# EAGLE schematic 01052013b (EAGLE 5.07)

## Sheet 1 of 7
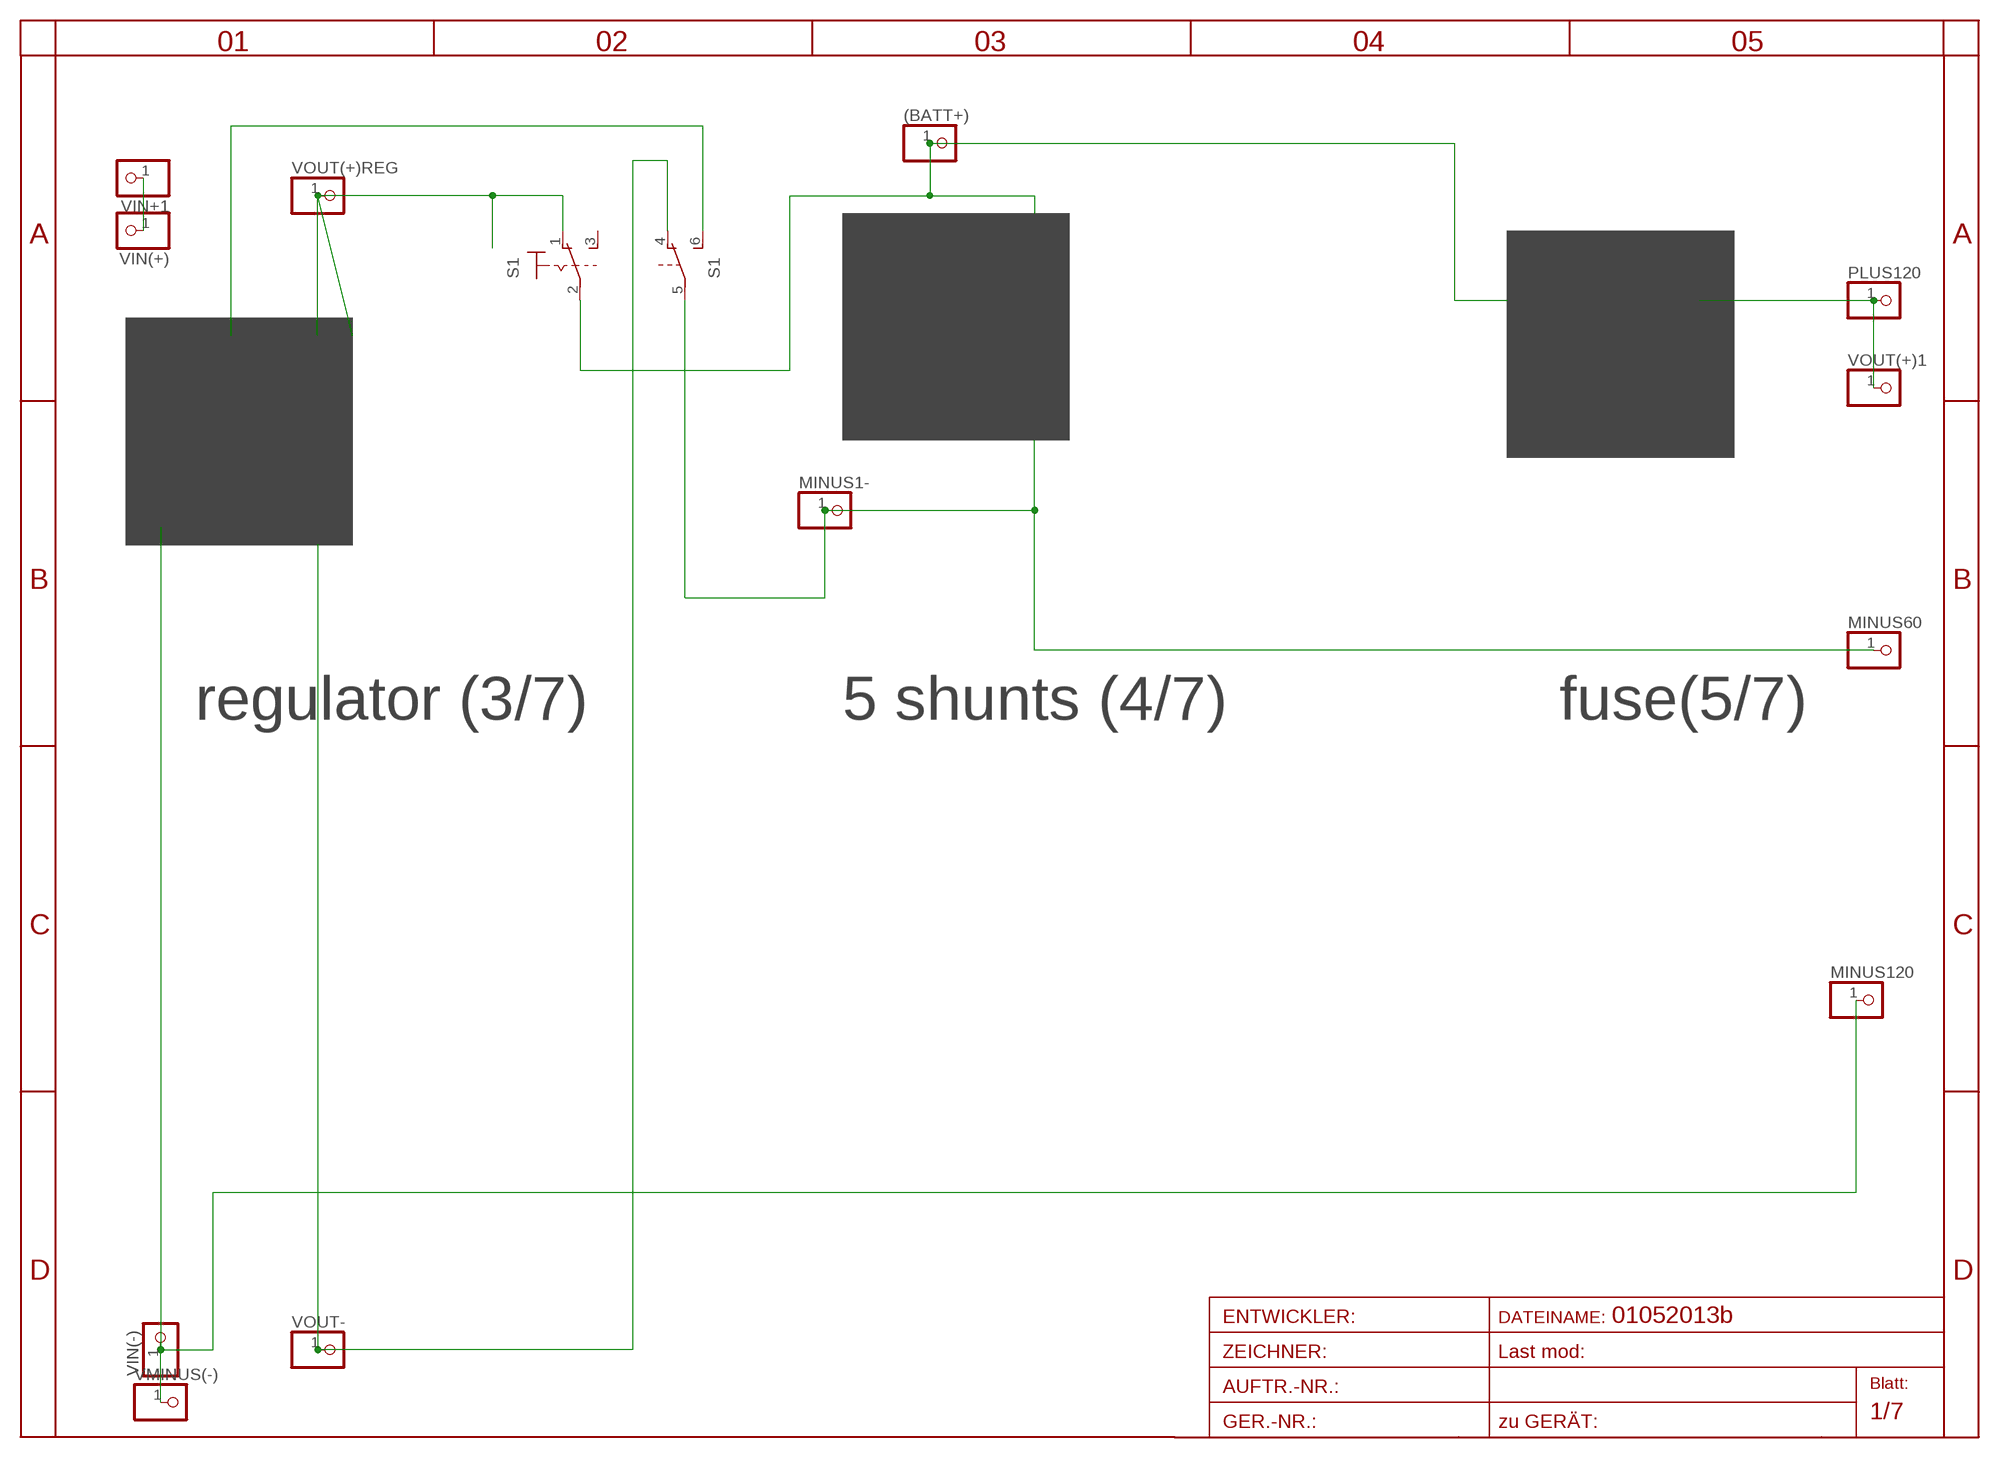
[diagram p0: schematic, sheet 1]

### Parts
(BATT+)  PINHD-1X14.5MM  [1X4MM5]
MINUS1-  PINHD-1X14.5MM  [1X4MM5]
MINUS60  PINHD-1X14.5MM  [1X4MM5]
MINUS120  PINHD-1X14.5MM  [1X4MM5]
PLUS120  PINHD-1X14.5MM  [1X4MM5]
S1  320-938320NEW  [320NEW]
VIN(+)  PINHD-1X11MM6  [1X1MM8]
VIN(-)  PINHD-1X1  [1X01]
VIN+1  PINHD-1X1  [1X01]
VMINUS(-)  PINHD-1X11MM6  [1X1MM8]
VOUT(+)1  PINHD-1X11X0.4  [1X01]
VOUT(+)REG  PINHD-1X11X0.4  [1X01]
VOUT-  PINHD-1X11X0.4  [1X01]

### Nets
BATT-: MINUS1-.1 MINUS60.1 S1.5(B:P) ; also sheet 4,5,6,7
IN-: MINUS120.1 VIN(-).1 VMINUS(-).1 ; also sheet 3
PLUS11: (BATT+).1 S1.2(1:P) ; also sheet 4,5,6,7
V+OUT: PLUS120.1 VOUT(+)1.1 ; also sheet 5
V-: S1.4(B:O) VOUT-.1 ; also sheet 3
VIN+: S1.6(B:S) ; also sheet 3
VINX: VIN(+).1 VIN+1.1 ; also sheet 3
VOUT+REG: S1.1(1:O) VOUT(+)REG.1 ; also sheet 3
Unconnected: S1.3(1:S)

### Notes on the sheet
- regulator (3/7) | 5 shunts (4/7) | fuse(5/7)

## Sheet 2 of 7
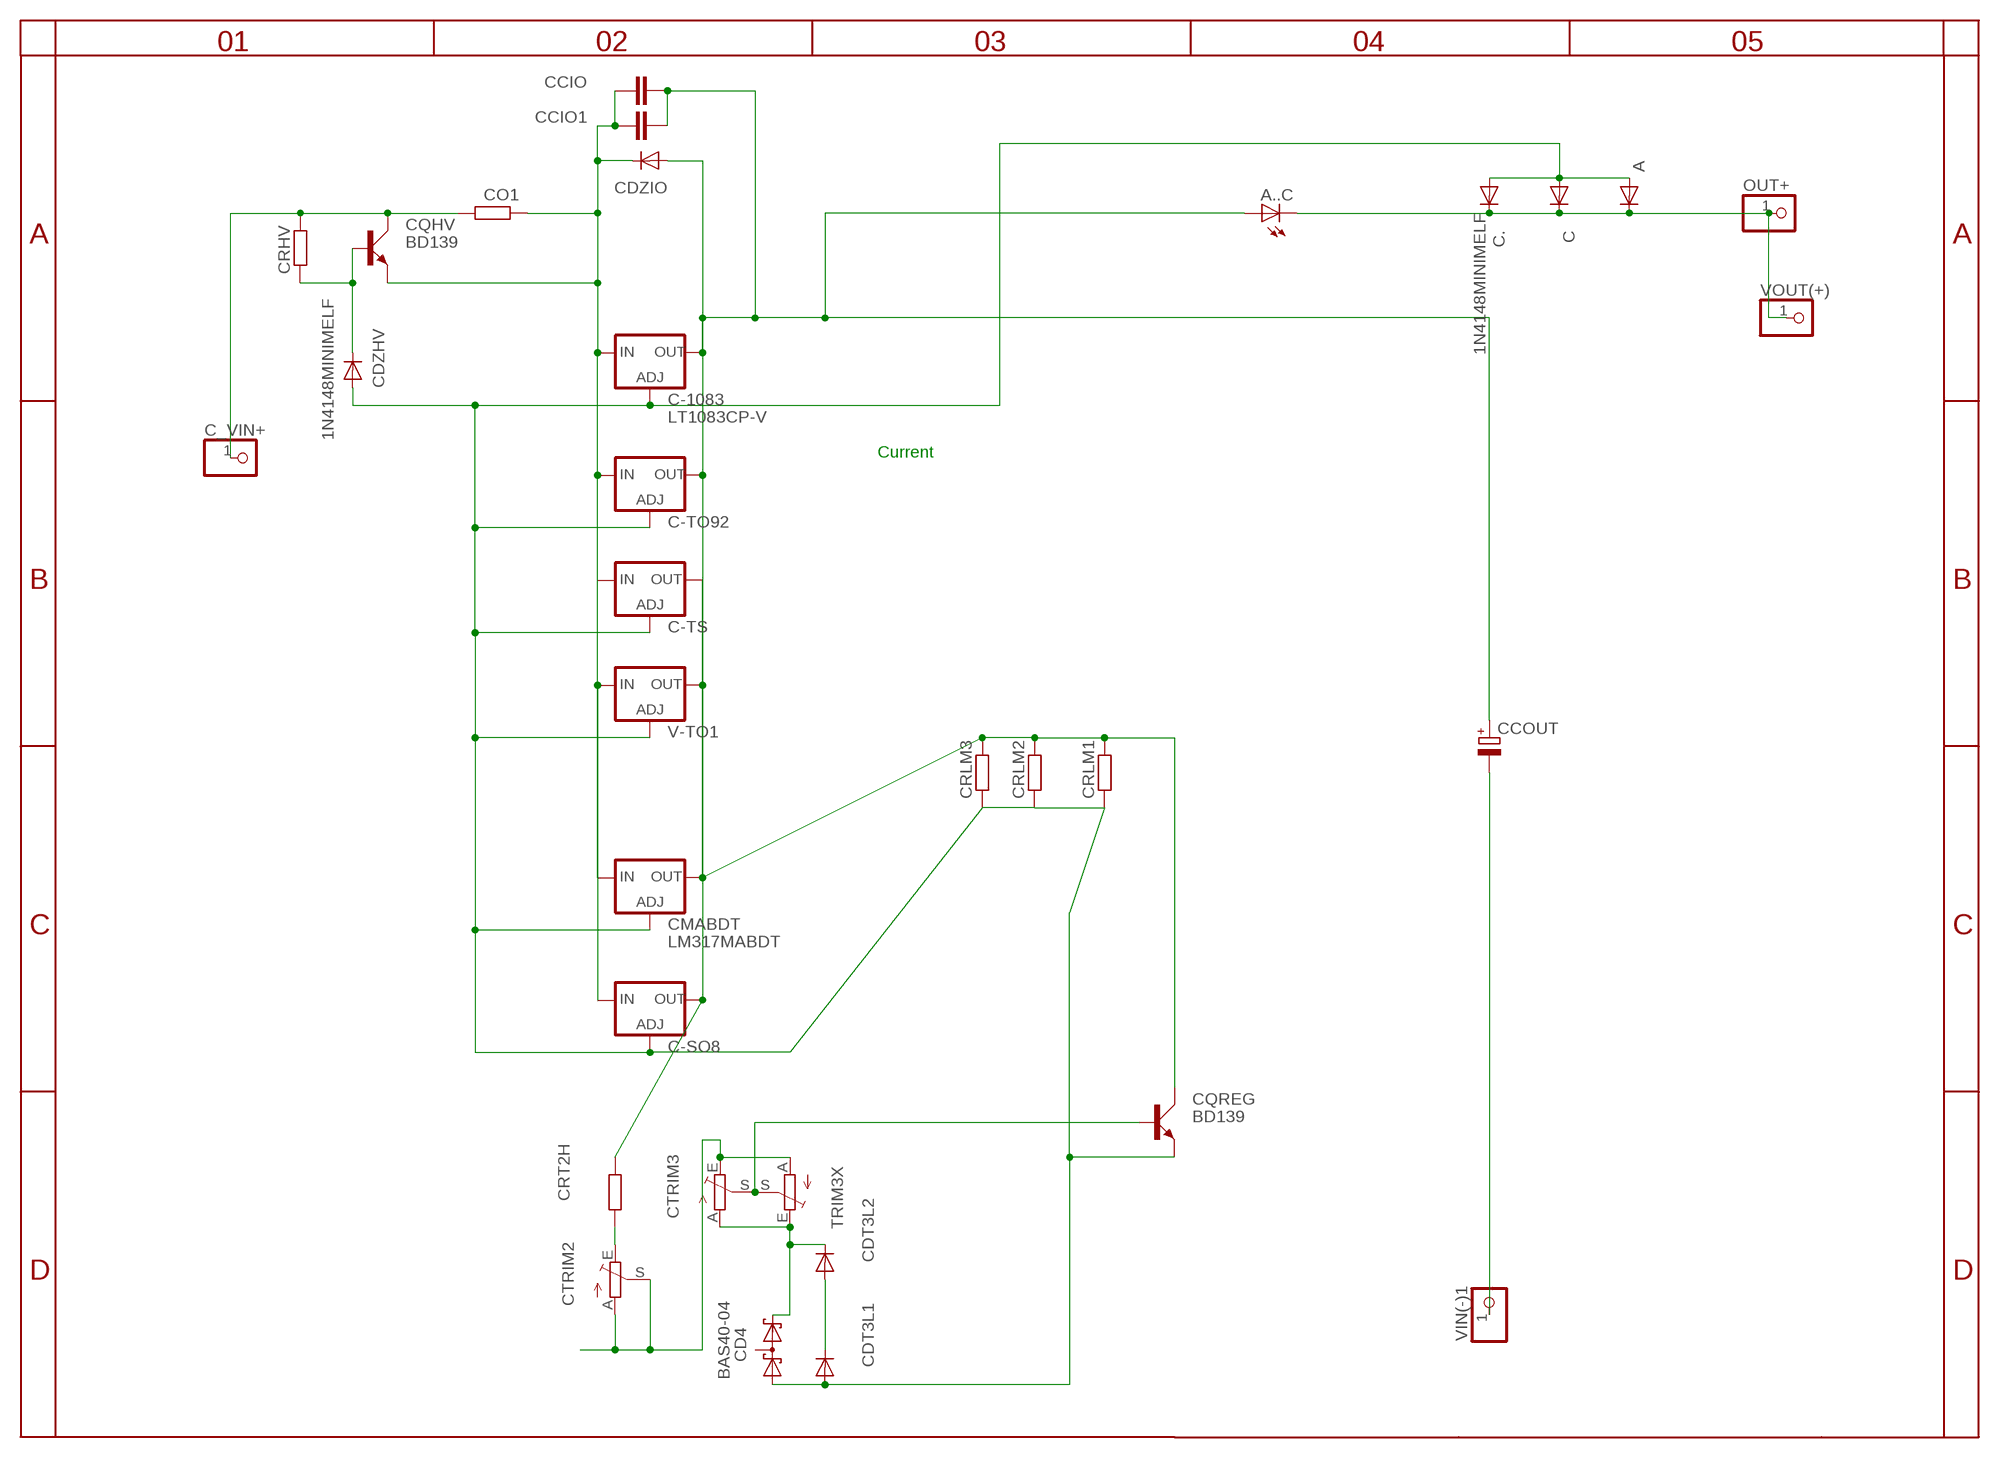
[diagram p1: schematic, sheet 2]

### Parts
A  DIODE-TO220V  [TO220ACS]
A..C  LED3MM  [LED3MM]
C  DIODE-SMB  [SMB]
C-1083  LT1083CP-V  [TO247S]
C-SO8  LM317LM-OUTPIN7  [SO08]
C-TO92  LM317LZS  [TO92S]
C-TS  LM317TS  [317TS]
C.  1N4148MINIMELF  [MINIMELF]
C_VIN+  PINHD-1X11MM6  [1X1MM8]
CCIO  C-EUC1206  [C1206]
CCIO1  C-EU050-025X075  [C050-025X075]
CCOUT  CPOL-EUE5-6  [E5-6]
CD4  BAS40-04  [SOT23]
CDT3L1  DIODE-MINIMELF  [MINIMELF]
CDT3L2  DIODE-MINIMELF  [MINIMELF]
CDZHV  1N4148MINIMELF  [MINIMELF]
CDZIO  DIODE-MINIMELF  [MINIMELF]
CMABDT  LM317MABDT  [DPACK]
CO1  R-EU_R0805  [R0805]
CQHV  BD139  [TO126AV]
CQREG  BD139  [TO126AV]
CRHV  R-EU_R1206  [R1206]
CRLM1  R-EU_R5025  [R5025]
CRLM2  R-EU_R1210  [R1210]
CRLM3  R-EU_R1206  [R1206]
CRT2H  R-EU_R1206  [R1206]
CTRIM2  TRIM_EU-EVND_H  [EVND8AA]
CTRIM3  TRIM_EU-EVND_H  [EVND8AA]
OUT+  PINHD-1X1  [1X01]
TRIM3X  TRIM_EU-RAND160  [RANDL]
V-TO1  LM317-TO3  [TO3-K02]
VIN(-)1  PINHD-1X1  [1X01]
VOUT(+)  PINHD-1X11X0.4  [1X01]

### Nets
ADJUST: A.A C-1083.1(ADJ) C-SO8.4(ADJ) C-TO92.1(ADJ) C-TS.1(ADJ) C..A C.A CD4.1(A1) CDT3L1.A CDZHV.A CMABDT.1(ADJ) CQREG.E CRLM1.1 CRLM2.1 CRLM3.1 V-TO1.2(ADJ)
B1: CQREG.B CTRIM3.S TRIM3X.S
CVIN: C_VIN+.1 CO1.2 CQHV.C CRHV.2
INPUT+: C-1083.3(IN) C-SO8.1(IN) C-TO92.3(IN) C-TS.3(IN) CCIO1.1 CCIO.1 CDZIO.C CMABDT.3(IN) CO1.1 CQHV.E V-TO1.1(IN)
MINUS: CD4.2(C2) CDT3L2.C CTRIM3.A TRIM3X.E
N$5: CTRIM2.A CTRIM2.S CTRIM3.E TRIM3X.A
N$6: CRT2H.1 CTRIM2.E
N$9: CCOUT.- VIN(-)1.1
N$54: CDT3L1.C CDT3L2.A
N$84: CDZHV.C CQHV.B CRHV.1
OUT1: A..C.A C-1083.2(OUT) C-SO8.7(OUT) C-TO92.2(OUT) C-TS.2(OUT) CCIO1.2 CCIO.2 CCOUT.+ CDZIO.A CMABDT.4(OUT) CQREG.C CRLM1.2 CRLM2.2 CRLM3.2 CRT2H.2 V-TO1.3(OUT)
OUT+: A..C.K(C) A.C C..C C.C OUT+.1 VOUT(+).1
Unconnected: CD4.3(C1A2)

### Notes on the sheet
- Current

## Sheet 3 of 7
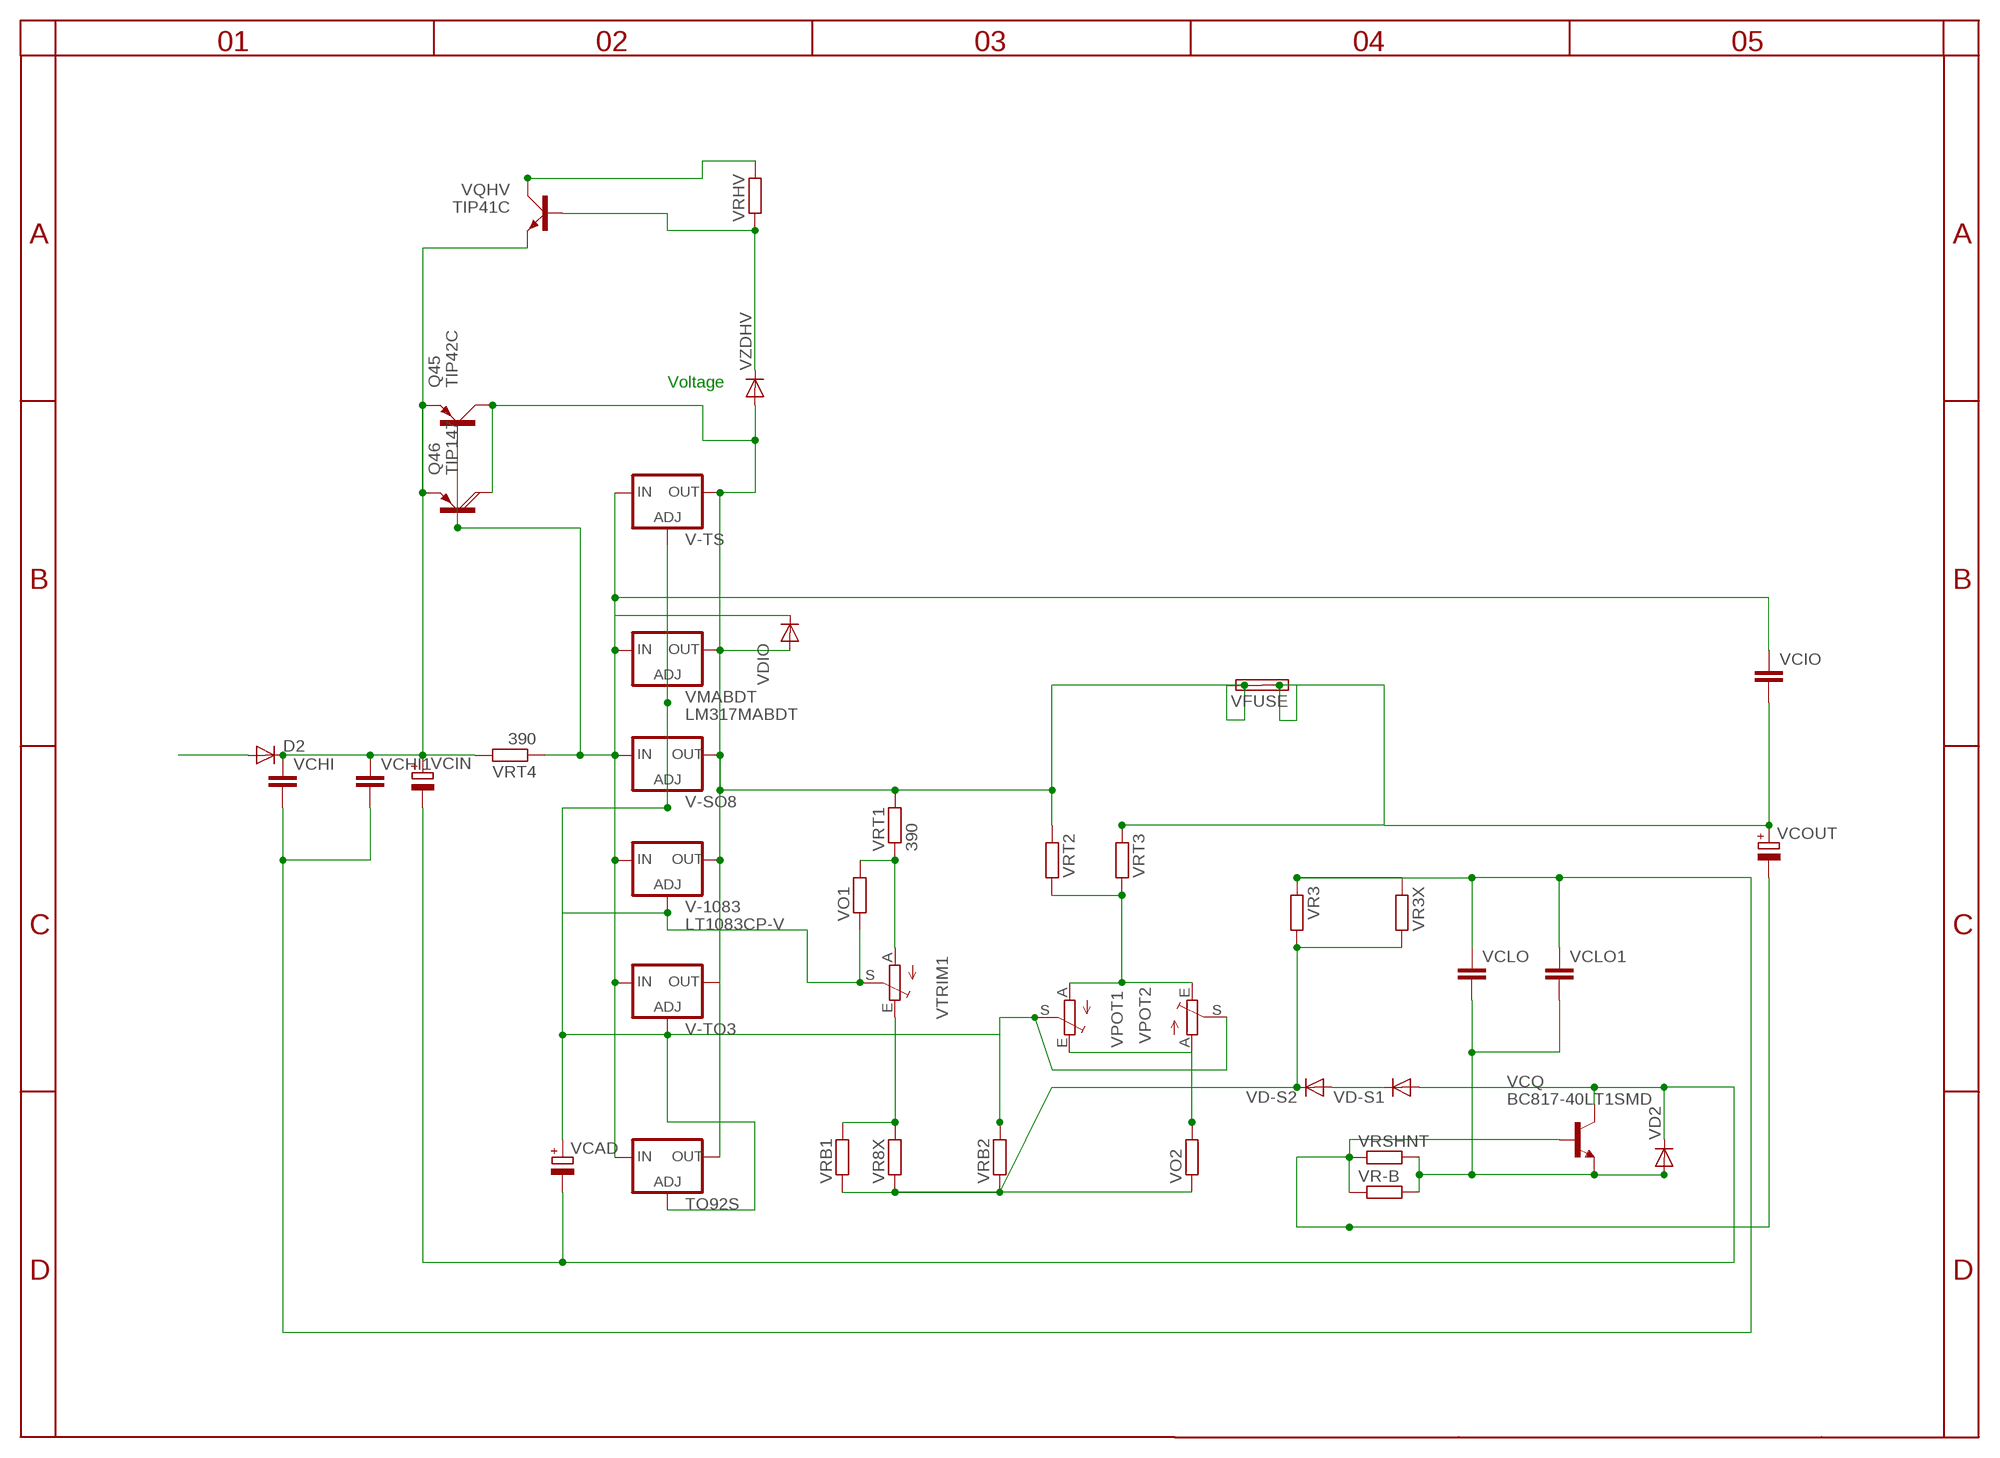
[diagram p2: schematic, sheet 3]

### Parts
D2  DIODE-SMC  [SMC]
Q45  TIP42C  [TO220AV]
Q46  TIP147  TIP147V  [SOT93V]
TO92S  LM317LZS  [TO92S]
V-1083  LT1083CP-V  [TO247S]
V-SO8  LM317LM-OUTPIN7  [SO08]
V-TO3  LM317-TO3  [TO3-K02]
V-TS  LM317TS  [317TS]
VCAD  CPOL-EUE2.5-6  [E2,5-6]
VCHI  C-EU050-025X075  [C050-025X075]
VCHI1  C-EUC1206  [C1206]
VCIN  CPOL-EUE2.5-6  [E2,5-6]
VCIO  C-EUC1206  [C1206]
VCLO  C-EU050-025X075  [C050-025X075]
VCLO1  C-EUC1206  [C1206]
VCOUT  CPOL-EUE5-8.5  [E5-8,5]
VCQ  BC817-40LT1SMD  [SOT23-BEC]
VD2  DIODE-MINIMELF  [MINIMELF]
VD-S1  DIODE-MINIMELF  [MINIMELF]
VD-S2  DIODE-MINIMELF  [MINIMELF]
VDIO  DIODE-MINIMELF  [MINIMELF]
VFUSE  SHK20Q  [SHK20Q]
VMABDT  LM317MABDT  [DPACK]
VO1  R-EU_0204/2V  [0204V]
VO2  R-EU_0204/2V  [0204V]
VPOT1  TRIM_EU-RAND160  [RANDL]
VPOT2  TRIM_EU-S64W  [S64W]
VQHV  TIP41C  [TO220AV]
VR3  R-EU_0204/5  [0204/5]
VR3X  R-EU_R1206  [R1206]
VR8X  R-EU_0204/2V  [0204V]
VR-B  R-EU_R2010  [R2010]
VRB1  R-EU_R1206  [R1206]
VRB2  R-EU_R1206  [R1206]
VRHV  R-EU_R1206  [R1206]
VRSHNT  R-EU_0617/17  [0617/17]
VRT1  390  R-EU_0207/15  [0207/15]
VRT2  R-EU_R1206  [R1206]
VRT3  R-EU_R1206  [R1206]
VRT4  390  R-EU_0207/10  [0207/10]
VTRIM1  TRIM_EU-EVND_H  [EVND8AA]
VZDHV  DIODE-MINIMELF  [MINIMELF]

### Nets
ADJ2: TO92S.1(ADJ) V-1083.1(ADJ) V-SO8.4(ADJ) V-TO3.2(ADJ) V-TS.1(ADJ) VCAD.+ VMABDT.1(ADJ) VO1.1 VPOT1.S VPOT2.S VRB2.2 VTRIM1.S
IN+1: Q45.B Q46.B TO92S.3(IN) V-1083.3(IN) V-SO8.1(IN) V-TO3.1(IN) V-TS.3(IN) VCIO.1 VDIO.C VMABDT.3(IN) VRT4.1
IN-: VCLO1.2 VCLO.2 VCQ.E VD2.A VR-B.2 VRSHNT.2 ; also sheet 1
N$1: VO2.2 VPOT1.E VPOT2.A
N$2: VPOT1.A VPOT2.E VRT2.2 VRT3.2
N$3: VR8X.2 VRB1.2 VTRIM1.E
N$4: VO1.2 VRT1.1 VTRIM1.A
N$7: VCHI1.2 VCHI.2 VCLO1.1 VCLO.1 VR3.1 VR3X.1
N$10: VQHV.B VRHV.1 VZDHV.C
N$12: VD-S2.C VO2.1 VR3.2 VR3X.2 VR8X.1 VRB1.1 VRB2.1
N$13: VD-S1.C VD-S2.A
N$166: D2.C Q45.E Q46.E VCHI1.1 VCHI.1 VCIN.+ VQHV.E VRT4.2
OUT2: Q45.C Q46.C TO92S.2(OUT) V-1083.2(OUT) V-SO8.7(OUT) V-TO3.3(OUT) V-TS.2(OUT) VDIO.A VFUSE.2A VFUSE.2B VMABDT.4(OUT) VRT1.2 VRT2.1 VZDHV.A
V-: VCOUT.- VCQ.B VR-B.1 VRSHNT.1 ; also sheet 1
VIN+: VQHV.C VRHV.2 ; also sheet 1
VINX: D2.A ; also sheet 1
VIRT-: VCAD.- VCIN.- VCQ.C VD2.C VD-S1.A
VOUT+REG: VCIO.2 VCOUT.+ VFUSE.1A VFUSE.1B VRT3.1 ; also sheet 1

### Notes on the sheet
- Voltage

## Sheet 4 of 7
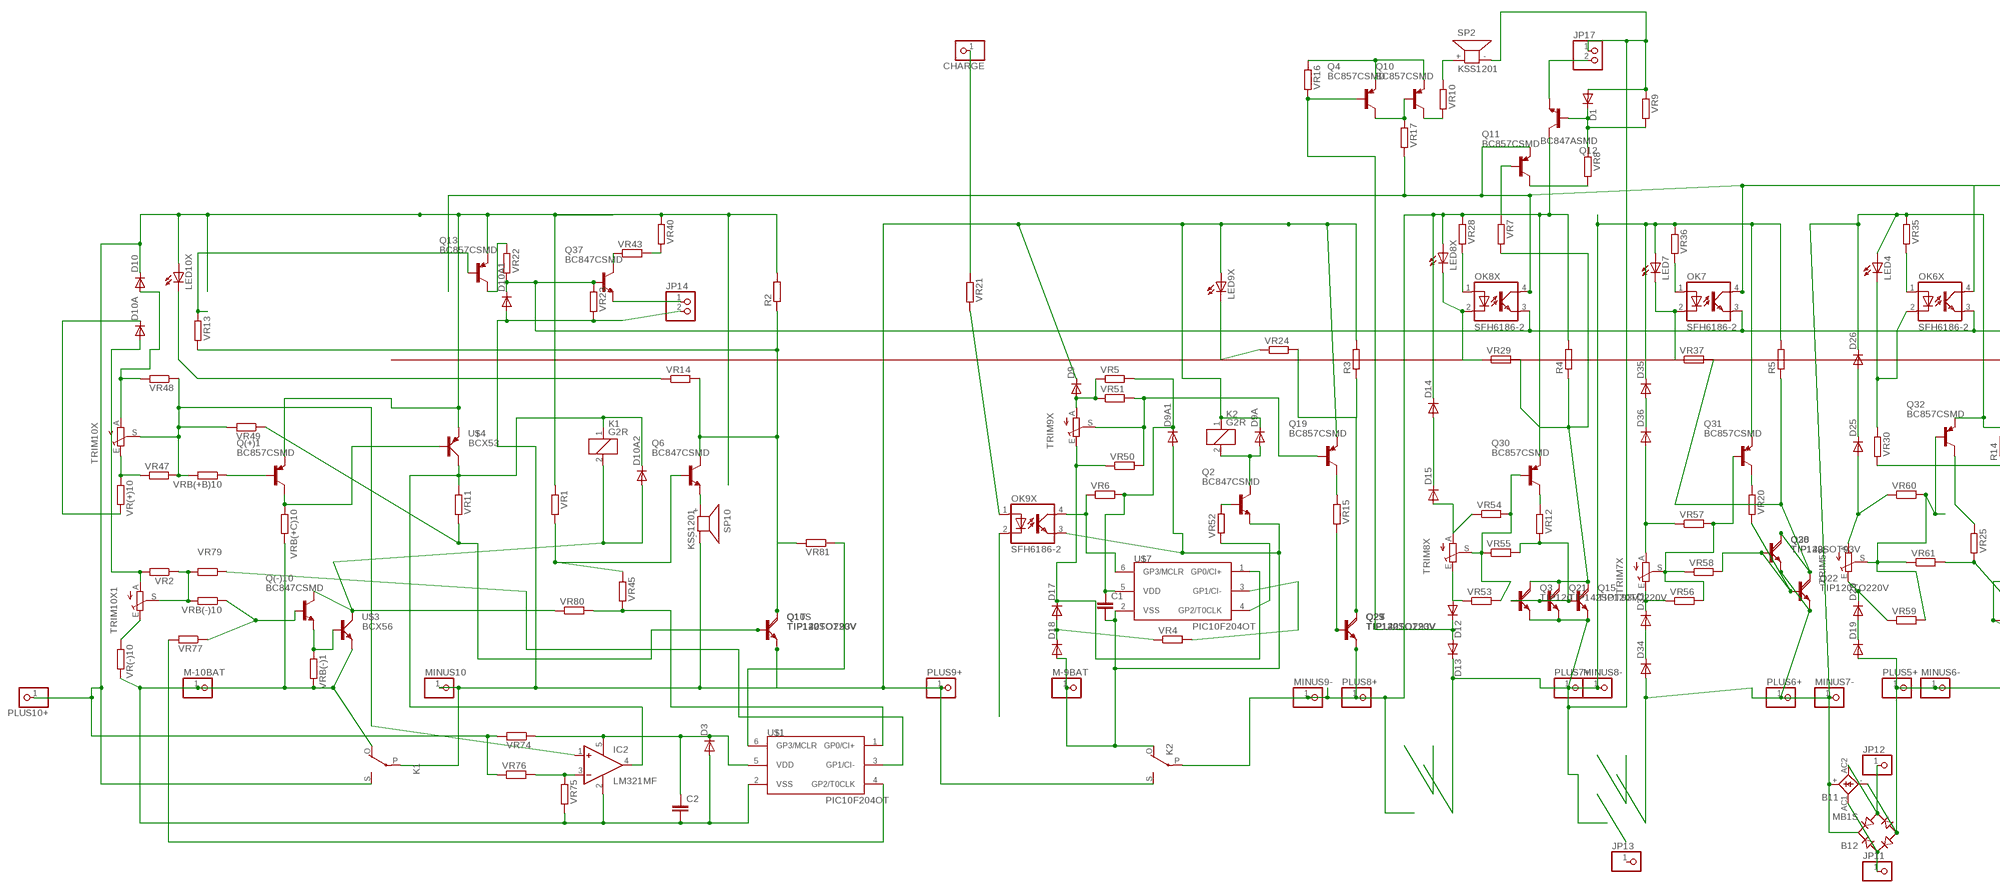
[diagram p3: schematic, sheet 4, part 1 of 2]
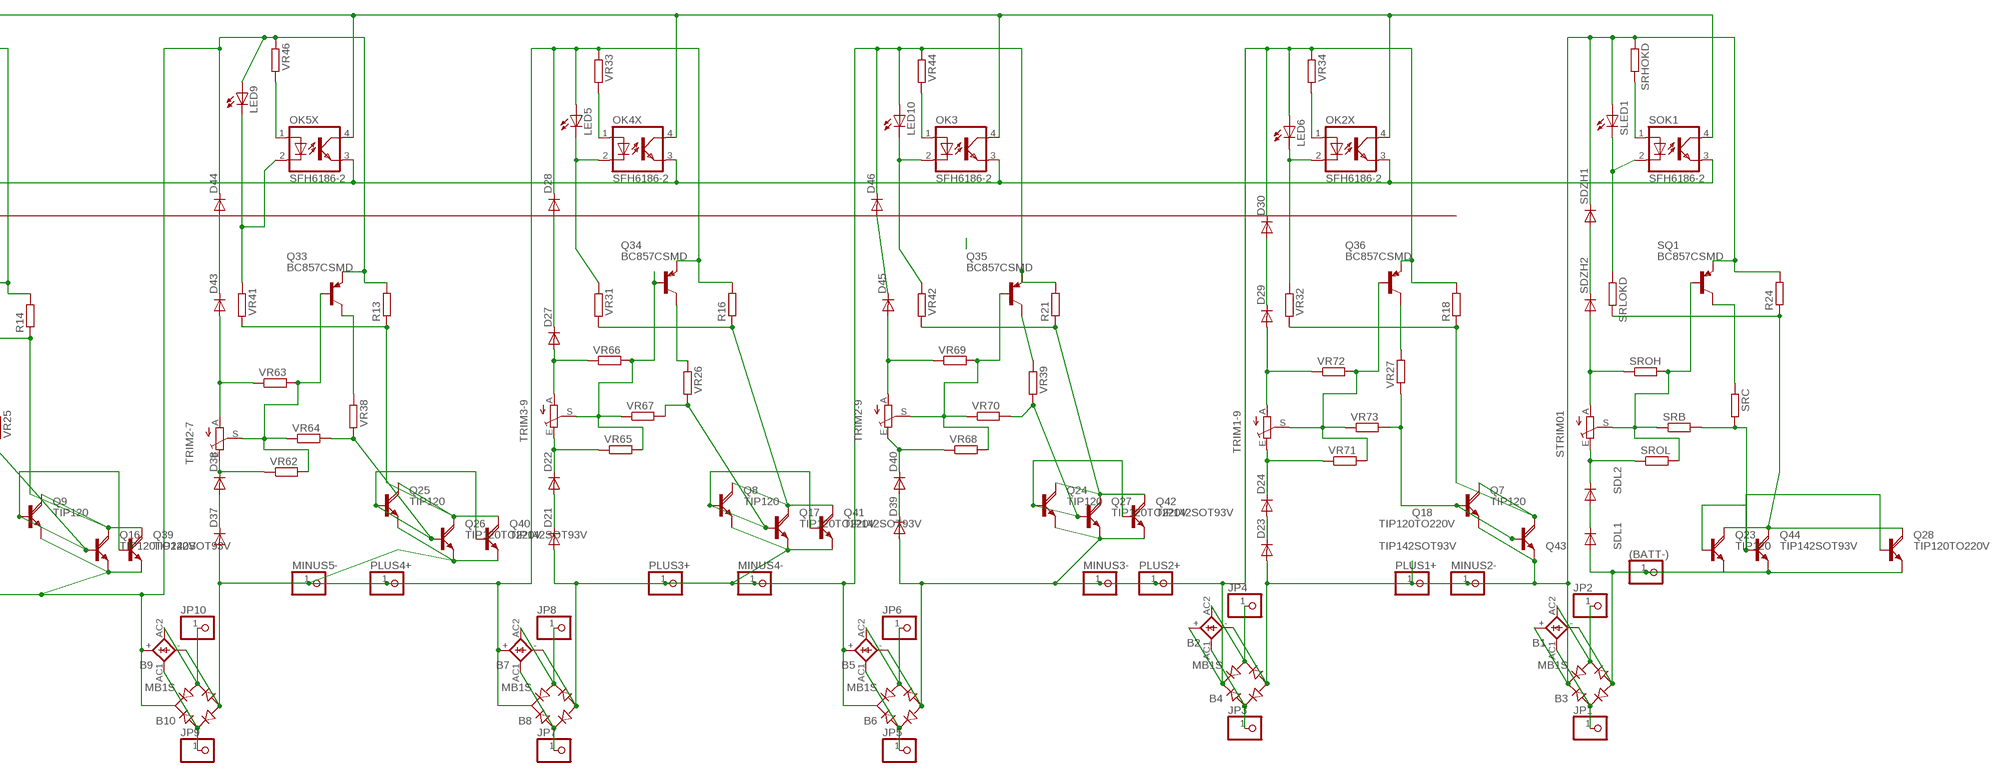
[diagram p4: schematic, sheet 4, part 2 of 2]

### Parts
(BATT-)  PINHD-1X11X0.4  [1X01]
B1  2KBP  [2KBP]
B2  2KBP  [2KBP]
B3  MB1S  [SOIC-4]
B4  MB1S  [SOIC-4]
B5  2KBP  [2KBP]
B6  MB1S  [SOIC-4]
B7  2KBP  [2KBP]
B8  MB1S  [SOIC-4]
B9  2KBP  [2KBP]
B10  MB1S  [SOIC-4]
B11  2KBP  [2KBP]
B12  MB1S  [SOIC-4]
C1  C-EUC0805  [C0805]
C2  C-EUC0805  [C0805]
CHARGE  PINHD-1X11X0.4  [1X01]
D1  DIODE-MINIMELF  [MINIMELF]
D3  DIODE-MINIMELF  [MINIMELF]
D9  DIODE-MINIMELF  [MINIMELF]
D9A  DIODE-MINIMELF  [MINIMELF]
D9A1  DIODE-MINIMELF  [MINIMELF]
D10  DIODE-MINIMELF  [MINIMELF]
D10A  DIODE-MINIMELF  [MINIMELF]
D10A1  DIODE-MINIMELF  [MINIMELF]
D10A2  DIODE-MINIMELF  [MINIMELF]
D12  DIODE-MINIMELF  [MINIMELF]
D13  DIODE-MINIMELF  [MINIMELF]
D14  DIODE-MINIMELF  [MINIMELF]
D15  DIODE-MINIMELF  [MINIMELF]
D17  DIODE-MINIMELF  [MINIMELF]
D18  DIODE-MINIMELF  [MINIMELF]
D19  DIODE-MINIMELF  [MINIMELF]
D20  DIODE-MINIMELF  [MINIMELF]
D21  DIODE-MINIMELF  [MINIMELF]
D22  DIODE-MINIMELF  [MINIMELF]
D23  DIODE-MINIMELF  [MINIMELF]
D24  DIODE-MINIMELF  [MINIMELF]
D25  DIODE-MINIMELF  [MINIMELF]
D26  DIODE-MINIMELF  [MINIMELF]
D27  DIODE-MINIMELF  [MINIMELF]
D28  DIODE-MINIMELF  [MINIMELF]
D29  DIODE-MINIMELF  [MINIMELF]
D30  DIODE-MINIMELF  [MINIMELF]
D33  DIODE-MINIMELF  [MINIMELF]
D34  DIODE-MINIMELF  [MINIMELF]
D35  DIODE-MINIMELF  [MINIMELF]
D36  DIODE-MINIMELF  [MINIMELF]
D37  DIODE-MINIMELF  [MINIMELF]
D38  DIODE-MINIMELF  [MINIMELF]
D39  DIODE-MINIMELF  [MINIMELF]
D40  DIODE-MINIMELF  [MINIMELF]
D43  DIODE-MINIMELF  [MINIMELF]
D44  DIODE-MINIMELF  [MINIMELF]
D45  DIODE-MINIMELF  [MINIMELF]
D46  DIODE-MINIMELF  [MINIMELF]
IC2  LM321MF  [SOT23-5]
JP1  PINHD-1X11X0.4  [1X01]
JP2  PINHD-1X11X0.4  [1X01]
JP3  PINHD-1X11X0.4  [1X01]
JP4  PINHD-1X11X0.4  [1X01]
JP5  PINHD-1X11X0.4  [1X01]
JP6  PINHD-1X11X0.4  [1X01]
JP7  PINHD-1X11X0.4  [1X01]
JP8  PINHD-1X11X0.4  [1X01]
JP9  PINHD-1X11X0.4  [1X01]
JP10  PINHD-1X11X0.4  [1X01]
JP11  PINHD-1X11X0.4  [1X01]
JP12  PINHD-1X11X0.4  [1X01]
JP13  PINHD-1X11X0.4  [1X01]
JP14  PINHD-1X2STR  [1X02]
JP17  PINHD-1X2STR  [1X02]
K1  G2R  [G2R]
K2  G2R  [G2R]
LED4  LEDCHIPLED_1206  [CHIPLED_1206]
LED5  LEDCHIPLED_1206  [CHIPLED_1206]
LED6  LEDCHIPLED_1206  [CHIPLED_1206]
LED7  LEDCHIPLED_1206  [CHIPLED_1206]
LED8X  LEDCHIPLED_1206  [CHIPLED_1206]
LED9  LEDCHIPLED_1206  [CHIPLED_1206]
LED9X  LEDCHIPLED_1206  [CHIPLED_1206]
LED10  LEDCHIPLED_1206  [CHIPLED_1206]
LED10X  LEDCHIPLED_1206  [CHIPLED_1206]
M-9BAT  PINHD-1X11X0.4  [1X01]
M-10BAT  PINHD-1X11X0.4  [1X01]
MINUS2-  PINHD-1X14.5MM  [1X4MM5]
MINUS3-  PINHD-1X14.5MM  [1X4MM5]
MINUS4-  PINHD-1X14.5MM  [1X4MM5]
MINUS5-  PINHD-1X14.5MM  [1X4MM5]
MINUS6-  PINHD-1X14.5MM  [1X4MM5]
MINUS7-  PINHD-1X14.5MM  [1X4MM5]
MINUS8-  PINHD-1X14.5MM  [1X4MM5]
MINUS9-  PINHD-1X14.5MM  [1X4MM5]
MINUS10  PINHD-1X14.5MM  [1X4MM5]
OK2X  SFH6186-2  [SMD4]
OK3  SFH6186-2  [SMD4]
OK4X  SFH6186-2  [SMD4]
OK5X  SFH6186-2  [SMD4]
OK6X  SFH6186-2  [SMD4]
OK7  SFH6186-2  [SMD4]
OK8X  SFH6186-2  [SMD4]
OK9X  SFH6186-2  [SMD4]
PLUS1+  PINHD-1X11X0.4  [1X01]
PLUS2+  PINHD-1X11X0.4  [1X01]
PLUS3+  PINHD-1X11X0.4  [1X01]
PLUS4+  PINHD-1X11X0.4  [1X01]
PLUS5+  PINHD-1X11X0.4  [1X01]
PLUS6+  PINHD-1X11X0.4  [1X01]
PLUS7+  PINHD-1X11X0.4  [1X01]
PLUS8+  PINHD-1X11X0.4  [1X01]
PLUS9+  PINHD-1X11X0.4  [1X01]
PLUS10+  PINHD-1X11X0.4  [1X01]
Q1  TIP142SOT93V  [SOT93V]
Q1T  TIP120TO220V  [TO220AV]
Q2  BC847CSMD  [SOT23]
Q2S  TIP120  TIP120DPAK  [D-PAK_TO252AA]
Q2T  TIP120TO220V  [TO220AV]
Q3  TIP120  TIP120DPAK  [D-PAK_TO252AA]
Q4  BC857CSMD  [SOT23-BEC]
Q6  BC847CSMD  [SOT23]
Q7  TIP120  TIP120DPAK  [D-PAK_TO252AA]
Q8  TIP120  TIP120DPAK  [D-PAK_TO252AA]
Q9  TIP120  TIP120DPAK  [D-PAK_TO252AA]
Q10  BC857CSMD  [SOT23-BEC]
Q10S  TIP120  TIP120DPAK  [D-PAK_TO252AA]
Q11  BC857CSMD  [SOT23-BEC]
Q12  BC847ASMD  [SOT23]
Q13  BC857CSMD  [SOT23-BEC]
Q15  TIP120TO220V  [TO220AV]
Q16  TIP120TO220V  [TO220AV]
Q17  TIP120TO220V  [TO220AV]
Q18  TIP120TO220V  [TO220AV]
Q19  BC857CSMD  [SOT23-BEC]
Q20  TIP120  TIP120DPAK  [D-PAK_TO252AA]
Q21  TIP142SOT93V  [SOT93V]
Q22  TIP120TO220V  [TO220AV]
Q23  TIP120  TIP120DPAK  [D-PAK_TO252AA]
Q24  TIP120  TIP120DPAK  [D-PAK_TO252AA]
Q25  TIP120  TIP120DPAK  [D-PAK_TO252AA]
Q26  TIP120TO220V  [TO220AV]
Q27  TIP120TO220V  [TO220AV]
Q28  TIP120TO220V  [TO220AV]
Q29  TIP142SOT93V  [SOT93V]
Q30  BC857CSMD  [SOT23-BEC]
Q31  BC857CSMD  [SOT23-BEC]
Q32  BC857CSMD  [SOT23-BEC]
Q33  BC857CSMD  [SOT23-BEC]
Q34  BC857CSMD  [SOT23-BEC]
Q35  BC857CSMD  [SOT23-BEC]
Q36  BC857CSMD  [SOT23-BEC]
Q37  BC847CSMD  [SOT23]
Q38  TIP142SOT93V  [SOT93V]
Q39  TIP142SOT93V  [SOT93V]
Q40  TIP142SOT93V  [SOT93V]
Q41  TIP142SOT93V  [SOT93V]
Q42  TIP142SOT93V  [SOT93V]
Q43  TIP142SOT93V  [SOT93V]
Q44  TIP142SOT93V  [SOT93V]
Q(+)1  BC857CSMD  [SOT23-BEC]
Q(-)10  BC847CSMD  [SOT23]
R2  R-EU_CERAM85  [CERAM85]
R3  R-EU_CERAM67  [CERAM67]
R4  R-EU_CERAM67  [CERAM67]
R5  R-EU_CERAM67  [CERAM67]
R13  R-EU_CERAM67  [CERAM67]
R14  R-EU_CERAM67  [CERAM67]
R16  R-EU_CERAM67  [CERAM67]
R18  R-EU_CERAM67  [CERAM67]
R21  R-EU_CERAM67  [CERAM67]
R24  R-EU_CERAM67  [CERAM67]
SDL1  DIODE-MINIMELF  [MINIMELF]
SDL2  DIODE-MINIMELF  [MINIMELF]
SDZH1  DIODE-MINIMELF  [MINIMELF]
SDZH2  DIODE-MINIMELF  [MINIMELF]
SLED1  LEDCHIPLED_1206  [CHIPLED_1206]
SOK1  SFH6186-2  [SMD4]
SP2  KSS1201  [KSS1201]
SP10  KSS1201  [KSS1201]
SQ1  BC857CSMD  [SOT23-BEC]
SRB  R-EU_R0805  [R0805]
SRC  R-EU_R1206  [R1206]
SRHOKD  R-EU_R1206  [R1206]
SRLOKD  R-EU_R1206  [R1206]
SROH  R-EU_R0805  [R0805]
SROL  R-EU_R0805  [R0805]
STRIM01  TRIM_EU-S64W  [S64W]
TRIM1-9  TRIM_EU-S64W  [S64W]
TRIM2-7  TRIM_EU-S64W  [S64W]
TRIM2-9  TRIM_EU-S64W  [S64W]
TRIM3-9  TRIM_EU-S64W  [S64W]
TRIM5X  TRIM_EU-S64W  [S64W]
TRIM7X  TRIM_EU-S64W  [S64W]
TRIM8X  TRIM_EU-S64W  [S64W]
TRIM9X  TRIM_EU-S64W  [S64W]
TRIM10X  TRIM_EU-S64W  [S64W]
TRIM10X1  TRIM_EU-S64W  [S64W]
U$1  PIC10F204OT  [SOT23-6]
U$3  BCX56  [SOT223]
U$4  BCX53  [SOT223]
U$7  PIC10F204OT  [SOT23-6]
VR1  R-EU_R0603  [R0603]
VR2  R-EU_R0603  [R0603]
VR4  R-EU_R0805  [R0805]
VR5  R-EU_R1206  [R1206]
VR6  R-EU_R0805  [R0805]
VR7  R-EU_R1206  [R1206]
VR8  R-EU_R1206  [R1206]
VR9  R-EU_R1206  [R1206]
VR10  R-EU_R1206  [R1206]
VR11  R-EU_R0603  [R0603]
VR12  R-EU_R1206  [R1206]
VR13  R-EU_R0603  [R0603]
VR14  R-EU_R0805  [R0805]
VR15  R-EU_R0805  [R0805]
VR16  R-EU_R1206  [R1206]
VR17  R-EU_R1206  [R1206]
VR20  R-EU_R1206  [R1206]
VR21  R-EU_R1206  [R1206]
VR22  R-EU_R0603  [R0603]
VR23  R-EU_R0603  [R0603]
VR24  R-EU_R0805  [R0805]
VR25  R-EU_R1206  [R1206]
VR26  R-EU_R1206  [R1206]
VR27  R-EU_R1206  [R1206]
VR28  R-EU_R1206  [R1206]
VR29  R-EU_R1206  [R1206]
VR30  R-EU_R1206  [R1206]
VR31  R-EU_R1206  [R1206]
VR32  R-EU_R1206  [R1206]
VR33  R-EU_R1206  [R1206]
VR34  R-EU_R1206  [R1206]
VR35  R-EU_R1206  [R1206]
VR36  R-EU_R1206  [R1206]
VR37  R-EU_R1206  [R1206]
VR38  R-EU_R1206  [R1206]
VR39  R-EU_R1206  [R1206]
VR40  R-EU_R1206  [R1206]
VR41  R-EU_R1206  [R1206]
VR42  R-EU_R1206  [R1206]
VR43  R-EU_R1206  [R1206]
VR44  R-EU_R1206  [R1206]
VR45  R-EU_R0603  [R0603]
VR46  R-EU_R1206  [R1206]
VR47  R-EU_R0603  [R0603]
VR48  R-EU_R0603  [R0603]
VR49  R-EU_R0603  [R0603]
VR50  R-EU_R0805  [R0805]
VR51  R-EU_R0805  [R0805]
VR52  R-EU_R1206  [R1206]
VR53  R-EU_R0805  [R0805]
VR54  R-EU_R0805  [R0805]
VR55  R-EU_R0805  [R0805]
VR56  R-EU_R0805  [R0805]
VR57  R-EU_R0805  [R0805]
VR58  R-EU_R0805  [R0805]
VR59  R-EU_R0805  [R0805]
VR60  R-EU_R0805  [R0805]
VR61  R-EU_R0805  [R0805]
VR62  R-EU_R0805  [R0805]
VR63  R-EU_R0805  [R0805]
VR64  R-EU_R0805  [R0805]
VR65  R-EU_R0805  [R0805]
VR66  R-EU_R0805  [R0805]
VR67  R-EU_R0805  [R0805]
VR68  R-EU_R0805  [R0805]
VR69  R-EU_R0805  [R0805]
VR70  R-EU_R0805  [R0805]
VR71  R-EU_R0805  [R0805]
VR72  R-EU_R0805  [R0805]
VR73  R-EU_R0805  [R0805]
VR74  R-EU_R0603  [R0603]
VR75  R-EU_R0603  [R0603]
VR76  R-EU_R0603  [R0603]
VR77  R-EU_R0603  [R0603]
VR79  R-EU_R0603  [R0603]
VR80  R-EU_R0603  [R0603]
VR81  R-EU_R0603  [R0603]
VR(+)10  R-EU_R1206  [R1206]
VR(-)10  R-EU_R1206  [R1206]
VRB(+B)10  R-EU_R0603  [R0603]
VRB(+C)10  R-EU_R0603  [R0603]
VRB(-)1  R-EU_R0603  [R0603]
VRB(-)10  R-EU_R0603  [R0603]

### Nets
B2: U$1.4(GP2/T0CLK) VR77.2
B10: IC2.1(+IN) TRIM10X.S VR47.2 VR48.1 VR49.2 VRB(+B)10.2
BATT-: (BATT-).1 B1.- B3.- OK9X.2(C) Q23.3(E) Q28.E Q44.E SDL1.A ; also sheet 1,5,6,7
E2: B1.+ B2.- B3.+ B4.- D23.A MINUS2-.1 PLUS1+.1 Q7.3(E) Q18.E Q43.E R24.2 SDZH1.C SLED1.A SQ1.E SRHOKD.1
E3: B2.+ B4.+ B5.- B6.- D30.C D39.A LED6.A MINUS3-.1 PLUS2+.1 Q24.3(E) Q27.E Q36.E Q42.E R18.2 VR34.1
E4: B5.+ B6.+ B7.- B8.- D21.A D46.C LED10.A MINUS4-.1 PLUS3+.1 Q8.3(E) Q17.E Q35.E Q41.E R21.2 VR44.1
E5: B7.+ B8.+ B9.- B10.- D28.C D37.A LED5.A MINUS5-.1 PLUS4+.1 Q25.3(E) Q26.E Q34.E Q40.E R16.2 VR33.1
E6: B9.+ B10.+ B11.- B12.- D19.A D44.C LED9.A MINUS6-.1 PLUS5+.1 Q9.3(E) Q16.E Q33.E Q39.E R13.2 VR46.1
E7: B11.+ B12.+ D26.C D34.A LED4.A MINUS7-.1 PLUS6+.1 Q20.3(E) Q22.E Q32.E Q38.E R14.2 VR35.1
E8: D1.A D13.C D35.C JP17.1 LED7.A MINUS8-.1 PLUS7+.1 Q3.3(E) Q15.E Q21.E Q31.E R5.2 SP2.- VR9.1 VR36.1
E9: D14.C K2.P(2:P) LED8X.A MINUS9-.1 PLUS8+.1 Q2S.3(E) Q2T.E Q12.3(C) Q29.E Q30.E R4.2 VR28.1
E10: D9.C D9A.C D10A1.A JP14.2 K1.P(2:P) K2.1 K2.S(2:S) LED9X.A MINUS10.1 PLUS9+.1 Q1.E Q1T.E Q10S.3(E) Q19.E R3.2 SP10.- VR23.2
GP3: Q6.2(E) SP10.+ ; also sheet 7
N$8: B1.AC1 B3.~1(AC1) JP1.1
N$11: LED10X.C VR14.1
N$14: D10.A TRIM10X.A VR48.2
N$15: D10A2.C IC2.4(OUT) K1.1 U$4.2(C) VR11.1
N$16: OK8X.1(A) VR28.2
N$17: D10A.A TRIM10X1.A VR2.2
N$20: D9.A TRIM9X.A VR5.1 VR51.1
N$22: TRIM10X1.S VR2.1 VR79.2 VRB(-)10.2
N$23: Q13.B VR13.1
N$24: TRIM10X1.E VR(-)10.1
N$25: Q1.B Q1T.B Q10S.1(B) VR11.2 VR49.1
N$26: D15.A TRIM8X.A VR54.1
N$27: D12.A TRIM8X.E VR53.1
N$29: D14.A D15.C
N$31: LED8X.C OK8X.2(C) VR29.1
N$32: D12.C D13.A Q4.B VR16.2
N$33: Q3.1(B) Q15.B Q21.B VR12.2 VR55.2
N$40: B1.AC2 B3.~2(AC2) JP2.1
N$45: Q35.C VR39.1
N$50: Q9.1(B) Q16.B Q39.B VR25.2 VR61.2
N$51: Q8.1(B) Q17.B Q41.B VR26.2 VR67.2
N$52: Q7.1(B) Q18.B Q43.B VR27.1 VR73.2
N$55: D33.A D34.C
N$56: C1.2 D9A1.A D18.A K2.O(2:O) M-9BAT.1 OK9X.3(EMIT) Q2.2(E) U$7.2(VSS)
N$57: D33.C TRIM7X.E VR56.1
N$58: B2.AC1 B4.~1(AC1) JP3.1
N$59: B2.AC2 B4.~2(AC2) JP4.1
N$60: B5.AC1 B6.~1(AC1) JP5.1
N$61: B5.AC2 B6.~2(AC2) JP6.1
N$62: D27.A TRIM3-9.A VR66.1
N$63: D22.C TRIM3-9.E VR65.1
N$64: Q34.B TRIM3-9.S VR65.2 VR66.2 VR67.1
N$65: Q31.B TRIM7X.S VR56.2 VR57.2 VR58.1
N$66: D25.A TRIM5X.A VR60.1
N$67: Q31.C VR20.1
N$68: D19.C D20.A
N$70: D21.C D22.A
N$71: D25.C D26.A
N$72: D20.C TRIM5X.E VR59.1
N$73: D27.C D28.A
N$74: D29.C D30.A
N$76: CHARGE.1 VR21.1
N$77: LED4.C OK6X.2(C) VR30.1
N$78: LED5.C OK4X.2(C) VR31.1
N$79: LED6.C OK2X.2(C) VR32.1
N$80: OK6X.1(A) VR35.2
N$81: OK4X.1(A) VR33.2
N$82: OK2X.1(A) VR34.2
N$85: B7.AC1 B8.~1(AC1) JP7.1
N$86: Q19.B TRIM9X.S VR50.2 VR51.2
N$87: Q2S.1(B) Q2T.B Q29.B VR15.2
N$88: D36.A TRIM7X.A VR57.1
N$89: D37.C D38.A
N$90: B7.AC2 B8.~2(AC2) JP8.1
N$91: D35.A D36.C
N$92: Q34.C VR26.1
N$93: Q20.1(B) Q22.B Q38.B VR20.2 VR58.2
N$94: LED9X.C VR24.1
N$95: OK9X.1(A) VR21.2
N$97: B9.AC1 B10.~1(AC1) JP9.1
N$98: B9.AC2 B10.~2(AC2) JP10.1
N$99: OK7.1(A) VR36.2
N$100: LED7.C OK7.2(C) VR37.1
N$102: Q25.1(B) Q26.B Q40.B VR38.2 VR64.2
N$103: Q24.1(B) Q27.B Q42.B VR39.2 VR70.2
N$104: Q23.1(B) Q28.B Q44.B SRB.2 SRC.2
N$105: Q32.B TRIM5X.S VR59.2 VR60.2 VR61.1
N$106: D43.A TRIM2-7.A VR63.1
N$107: Q33.C VR38.1
N$108: D29.A TRIM1-9.A VR72.1
N$109: D40.C TRIM2-9.E VR68.1
N$110: D38.C TRIM2-7.E VR62.1
N$111: Q33.B TRIM2-7.S VR62.2 VR63.2 VR64.1
N$112: Q32.C VR25.1
N$113: Q35.B TRIM2-9.S VR68.2 VR69.2 VR70.1
N$114: B11.AC1 B12.~1(AC1) JP11.1
N$115: D45.A TRIM2-9.A VR69.1
N$116: D24.C TRIM1-9.E VR71.1
N$117: B11.AC2 B12.~2(AC2) JP12.1
N$118: D43.C D44.A
N$119: D45.C D46.A
N$120: SDZH1.A SDZH2.C
N$121: LED9.C OK5X.2(C) VR41.1
N$122: LED10.C OK3.2(C) VR42.1
N$123: SLED1.C SOK1.2(C) SRLOKD.1
N$124: OK5X.1(A) VR46.2
N$125: OK3.1(A) VR44.2
N$126: SOK1.1(A) SRHOKD.2
N$127: D17.C TRIM9X.E U$7.1(GP0/CI+) VR50.1
N$128: TRIM10X.E VR47.1 VR(+)10.1
N$129: D17.A D18.C VR4.1
N$130: Q30.C VR12.1
N$131: Q19.C VR15.1
N$132: Q30.B TRIM8X.S VR53.2 VR54.2 VR55.1
N$133: D39.C D40.A
N$134: Q36.B TRIM1-9.S VR71.2 VR72.2 VR73.1
N$136: JP14.1 Q37.2(E)
N$137: D23.C D24.A
N$138: U$1.1(GP0/CI+) VR45.2 VR80.2
N$140: Q36.C VR27.2
N$141: SDZH2.A SROH.1 STRIM01.A
N$142: SDL2.C SROL.1 STRIM01.E
N$143: SQ1.B SRB.1 SROH.2 SROL.2 STRIM01.S
N$144: SDL1.C SDL2.A
N$145: SQ1.C SRC.1
N$146: Q6.1(B) VR1.2 VR45.1
N$147: Q2.1(B) VR52.2
N$148: D9A.A K2.2 Q2.3(C)
N$149: IC2.3(-IN) VR75.1 VR76.2
N$150: SP2.+ VR10.1
N$151: U$7.4(GP2/T0CLK) VR52.1
N$152: D1.C Q12.1(B) VR8.1 VR9.2
N$153: OK9X.4(COL) U$7.6(GP3/MCLR) VR6.1
N$154: U$7.3(GP1/CI-) VR4.2
N$155: Q11.C VR8.2
N$156: C1.1 D9A1.C U$7.5(VDD) VR5.2 VR6.2
N$157: JP17.2 Q12.2(E)
N$158: Q11.B VR7.1
N$159: Q13.C VR22.1
N$160: Q4.E Q10.E VR16.1
N$161: Q4.C Q10.B VR17.1
N$162: Q10.C VR10.2
N$163: VR40.2 VR43.2
N$164: Q37.3(C) VR43.1
N$165: U$1.3(GP1/CI-) VR79.1
N$167: Q(+)1.B VRB(+B)10.1
N$168: Q(-)10.1(B) VR77.1 VRB(-)10.1
N$169: D10A2.A K1.2 Q(-)10.3(C) U$3.2(C) VR80.1
N$170: U$1.6(GP3/MCLR) VR81.1
N$171: Q(+)1.C U$4.1(B) VRB(+C)10.1
N$172: D10A.C VR(+)10.2
N$173: Q(-)10.2(E) U$3.1(B) VRB(-)1.1
PLUS11: D10.C K1.S(2:S) LED10X.A PLUS10+.1 Q13.E Q(+)1.E R2.2 U$4.3(E) VR1.1 VR40.1 VR74.2 VR76.1 ; also sheet 1,5,6,7
Q0C: Q23.4(C) Q28.C Q44.C R24.1 SRLOKD.2
Q2C: Q7.4(C) Q18.C Q43.C R18.1 VR32.2
Q3C: Q24.4(C) Q27.C Q42.C R21.1 VR42.2
Q4C: Q8.4(C) Q17.C Q41.C R16.1 VR31.2
Q5C: Q25.4(C) Q26.C Q40.C R13.1 VR41.2
Q6C: Q9.4(C) Q16.C Q39.C R14.1 VR30.2
Q7C: Q20.4(C) Q22.C Q38.C R5.1 VR37.2
Q8C: Q3.4(C) Q15.C Q21.C R4.1 VR7.2 VR29.2
Q9C: Q2S.4(C) Q2T.C Q29.C R3.1 VR24.2
Q10C: Q1.C Q1T.C Q6.3(C) Q10S.4(C) R2.1 VR13.2 VR14.2 VR81.2
V3: C2.1 D3.C IC2.5(V+) U$1.5(VDD) VR74.1
VENTB: D10A1.C OK2X.3(EMIT) OK3.3(EMIT) OK4X.3(EMIT) OK5X.3(EMIT) OK6X.3(EMIT) OK7.3(EMIT) OK8X.3(EMIT) Q37.1(B) SOK1.3(EMIT) VR22.2 VR23.1 ; also sheet 6
VENTMID: OK2X.4(COL) OK3.4(COL) OK4X.4(COL) OK5X.4(COL) OK6X.4(COL) OK7.4(COL) OK8X.4(COL) Q11.E SOK1.4(COL) VR17.2 ; also sheet 6
VSS: C2.2 D3.A IC2.2(V-) K1.O(2:O) M-10BAT.1 U$1.2(VSS) U$3.3(E) VR75.2 VR(-)10.2 VRB(+C)10.2 VRB(-)1.2
Unconnected: JP13.1

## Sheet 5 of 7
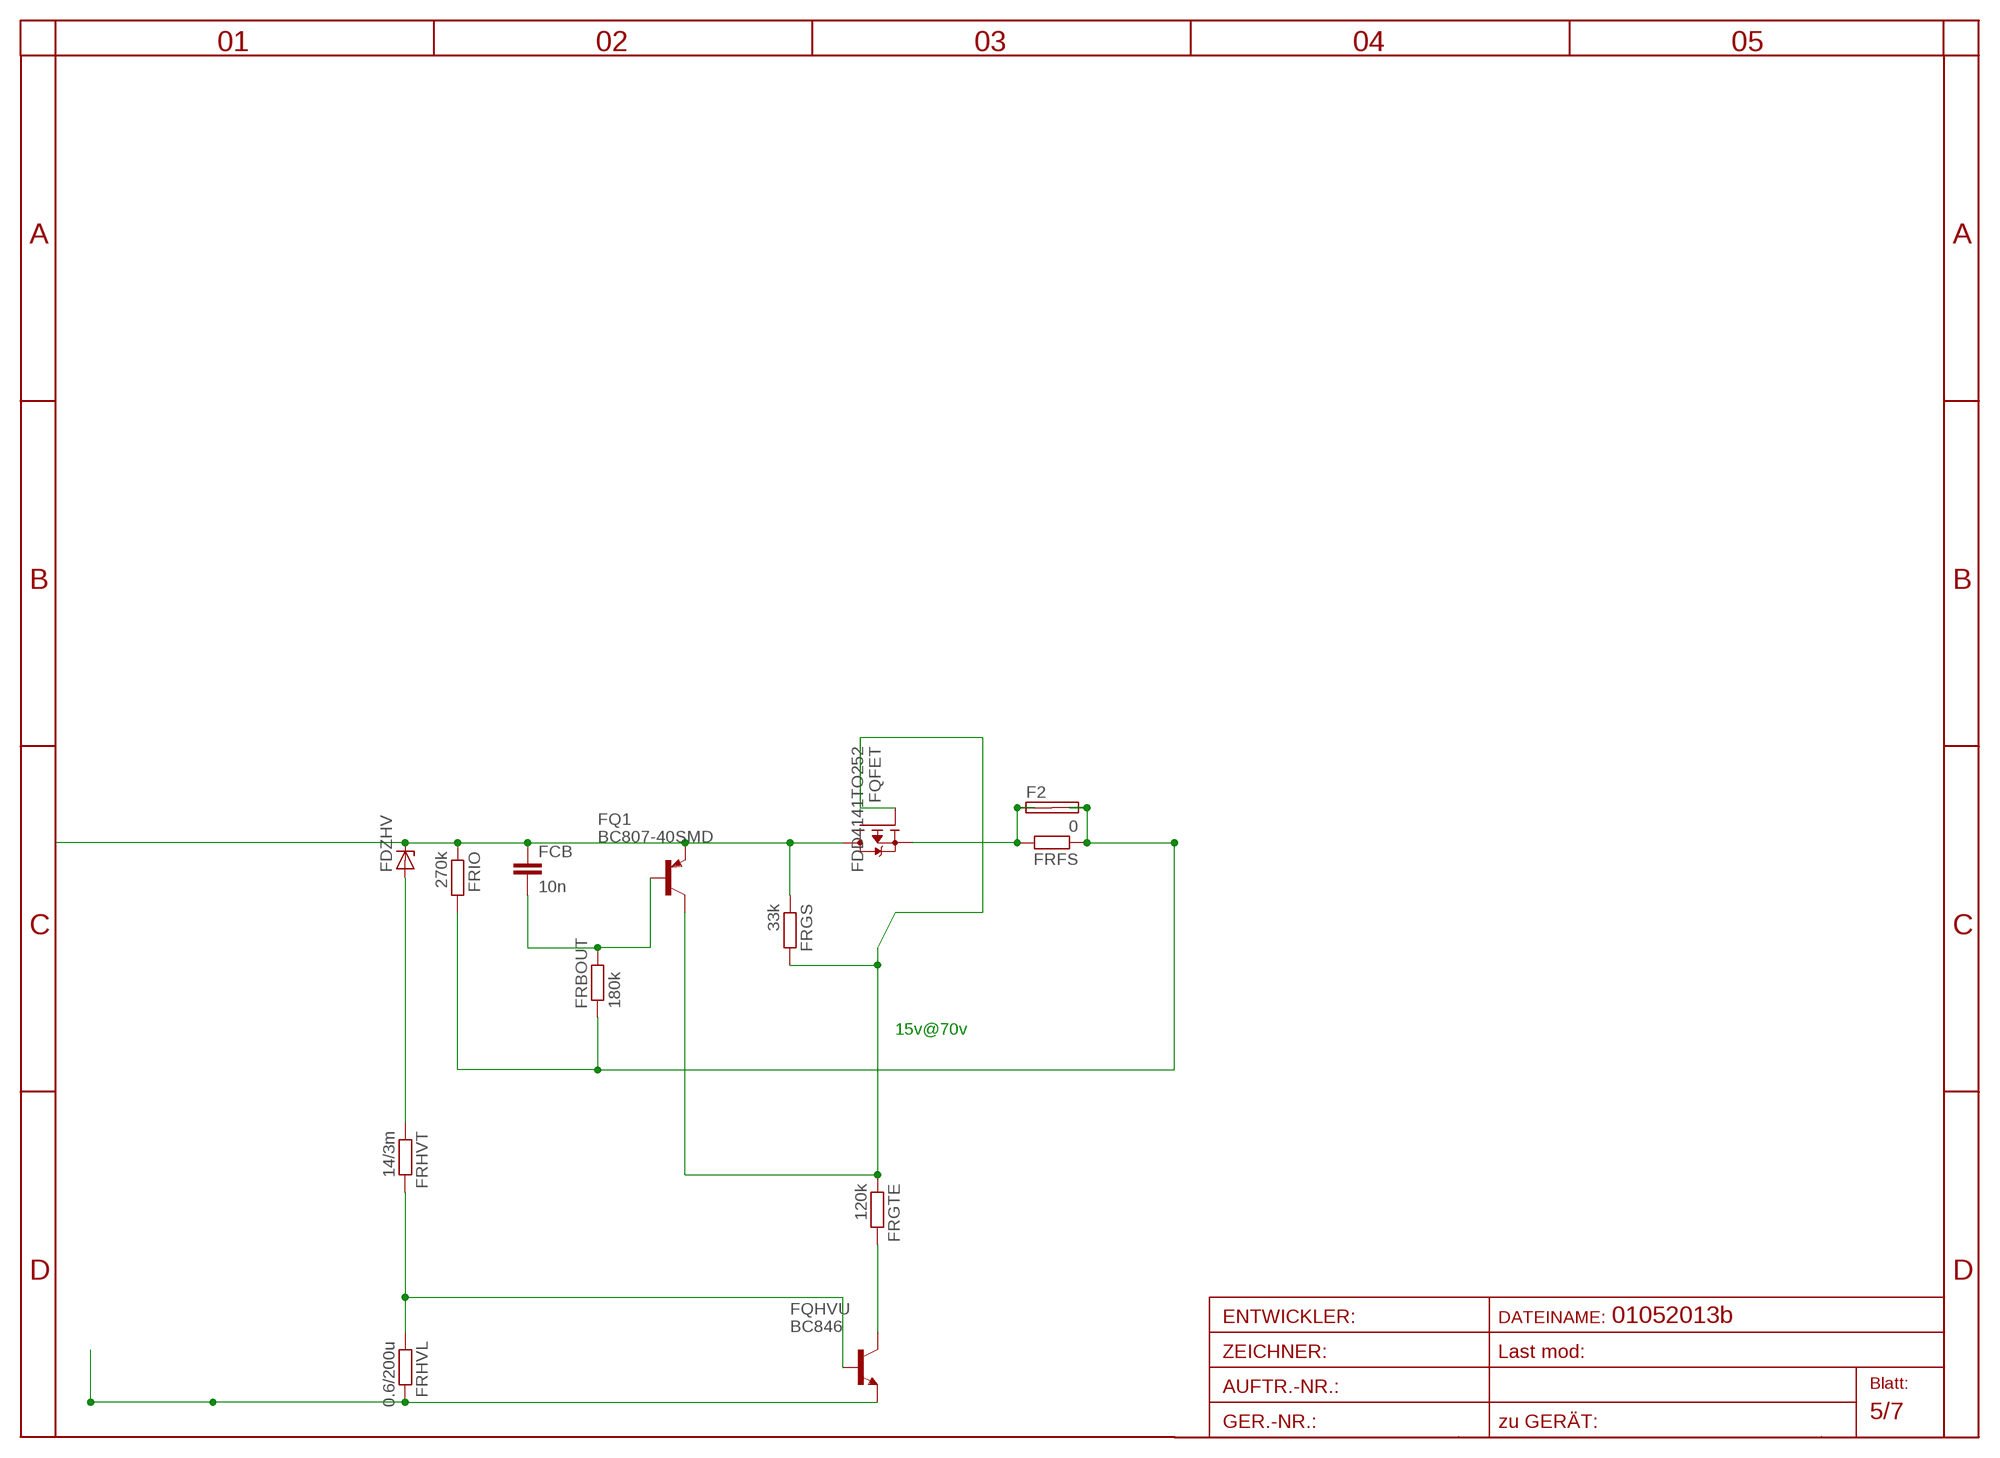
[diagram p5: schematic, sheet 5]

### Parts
F2  SHK20Q  [SHK20Q]
FCB  10n  C-EUC1206  [C1206]
FDZHV  ZENER-DIODESOD80C  [SOD80C]
FQ1  BC807-40SMD  [SOT23-BEC]
FQFET  FDD4141TO252  [TO252]
FQHVU  BC846  [SOT23]
FRBOUT  180k  R-EU_R1206  [R1206]
FRFS  0  R-EU_0207/15  [0207/15]
FRGS  33k  R-EU_R1206  [R1206]
FRGTE  120k  R-EU_R1206  [R1206]
FRHVL  0.6/200u  R-EU_R1206  [R1206]
FRHVT  14/3m  R-EU_R1206  [R1206]
FRIO  270k  R-EU_R1206  [R1206]

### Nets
B-Q1: FCB.2 FQ1.B FRBOUT.2
BATT-: FQHVU.2(E) FRHVL.2 ; also sheet 1,4,6,7
D: F2.1A F2.1B FQFET.3(S) FRFS.2
GATE: FQ1.C FQFET.1(G) FRGS.2 FRGTE.1
N$18: FQHVU.3(C) FRGTE.2
N$19: FDZHV.A FRHVT.1
N$21: FQHVU.1(B) FRHVL.1 FRHVT.2
PLUS11: FCB.1 FDZHV.C FQ1.E FQFET.2(D) FRGS.1 FRIO.1 ; also sheet 1,4,6,7
V+OUT: F2.2A F2.2B FRBOUT.1 FRFS.1 FRIO.2 ; also sheet 1

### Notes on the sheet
- 15v@70v

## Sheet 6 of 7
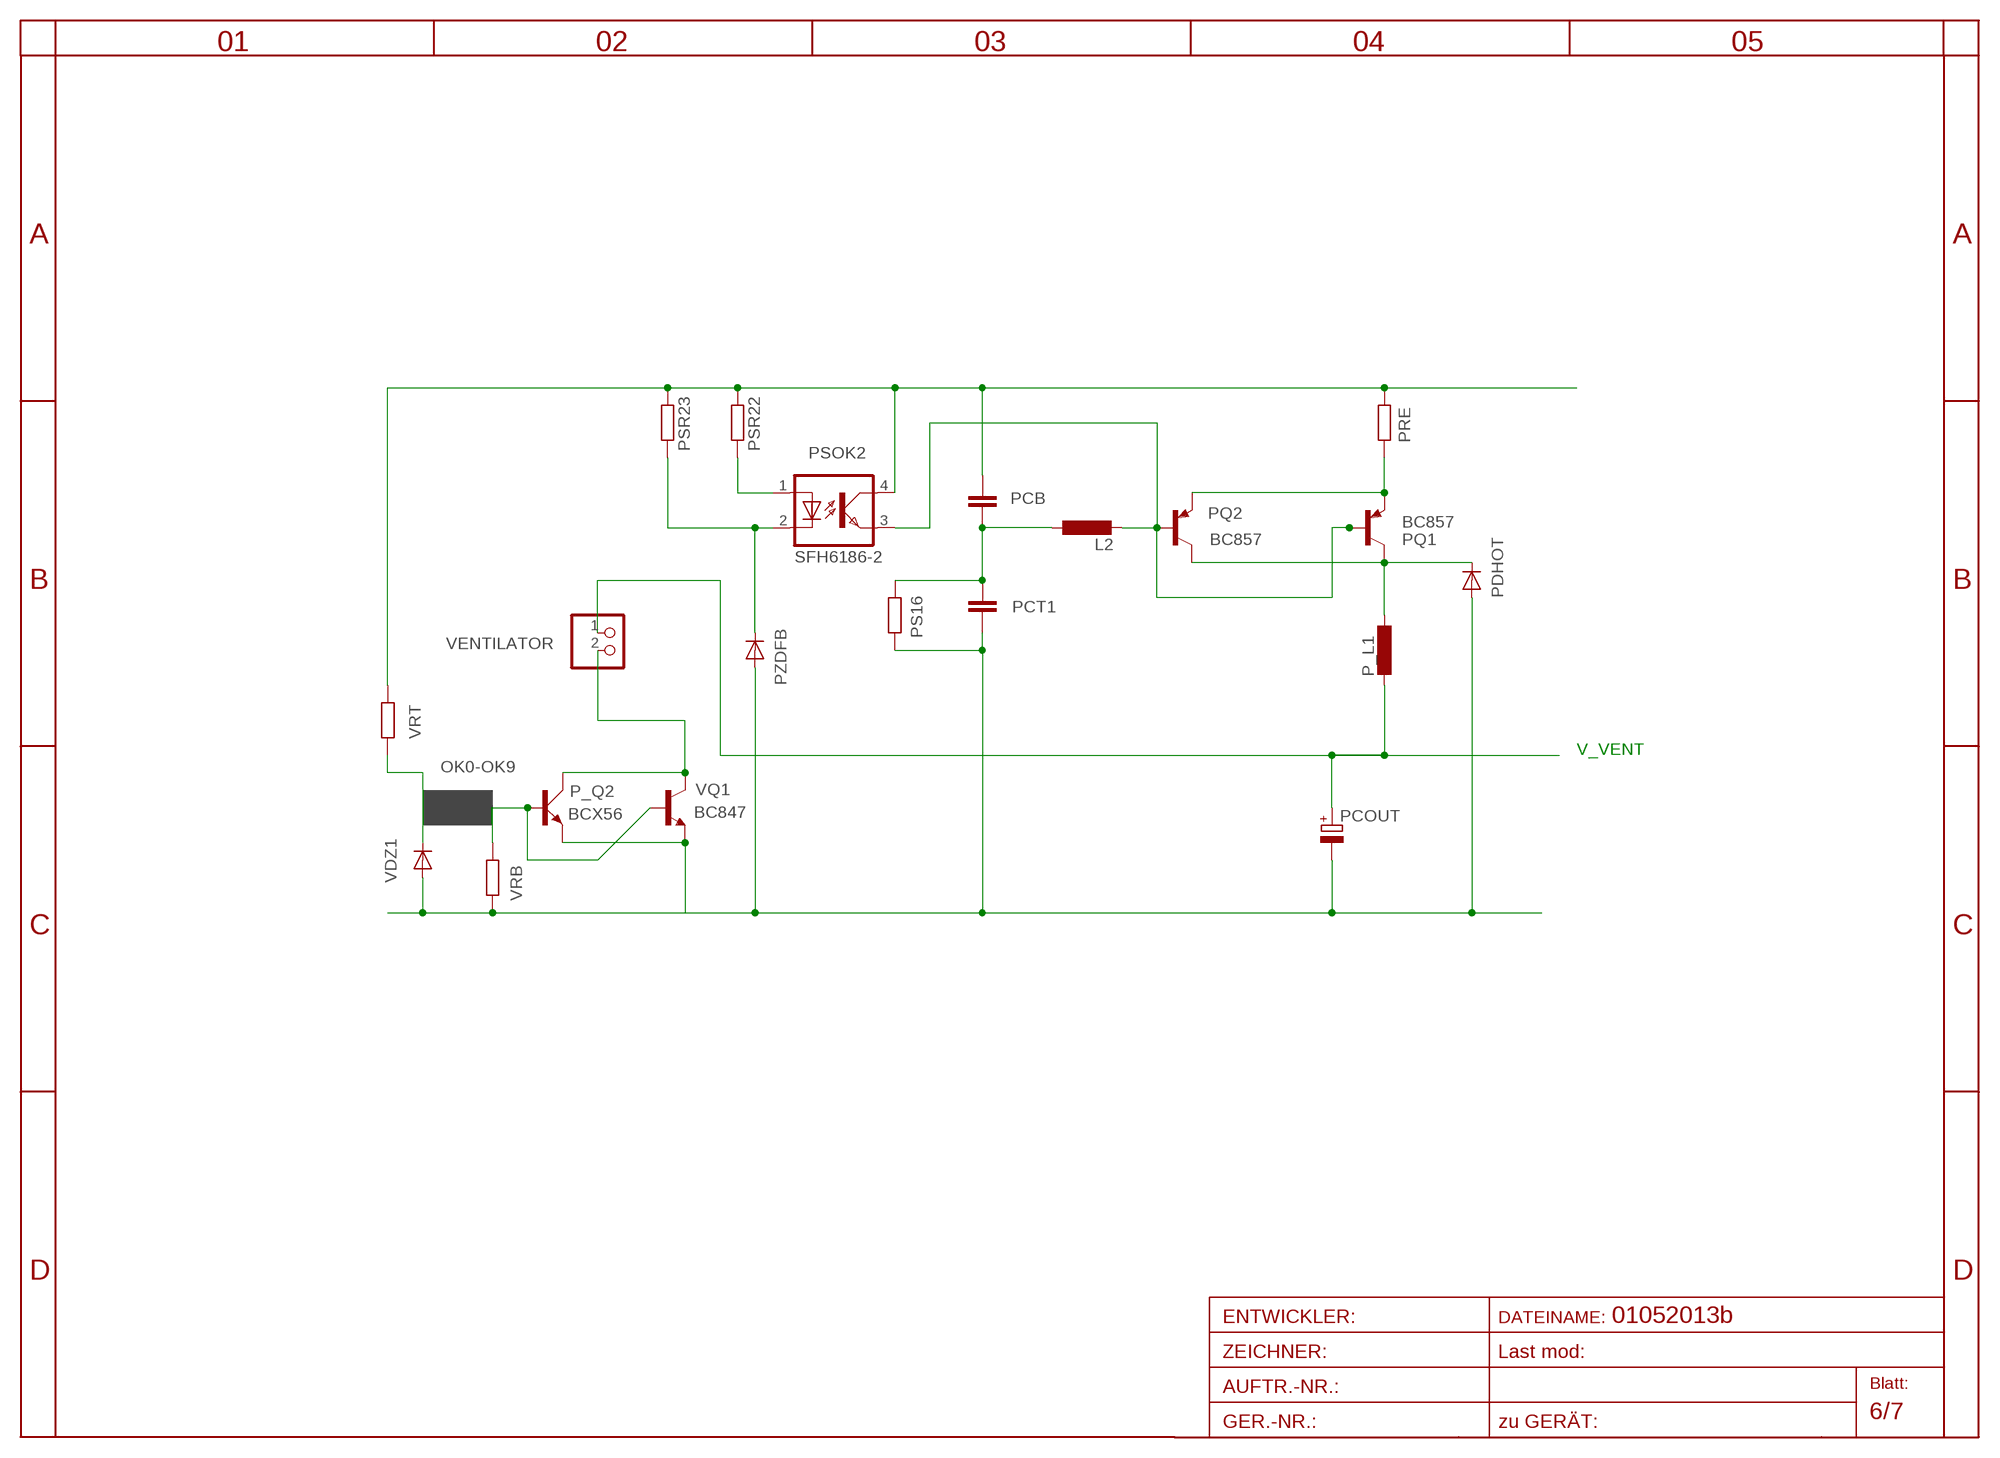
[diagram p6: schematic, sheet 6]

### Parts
L2  L-EUL5650M  [L5650M]
P_L1  L-EUL5650M  [L5650M]
P_Q2  BCX56  [SOT223]
PCB  C-EUC1206  [C1206]
PCOUT  CPOL-EUE2.5-6  [E2,5-6]
PCT1  C-EUC1206  [C1206]
PDHOT  DIODE-SMB  [SMB]
PQ1  BC857  [SOT223]
PQ2  BC857  BC857CSMD  [SOT23-BEC]
PRE  R-EU_R1210  [R1210]
PS16  R-EU_R1206  [R1206]
PSOK2  SFH6186-2  [SMD4]
PSR22  R-EU_R1206  [R1206]
PSR23  R-EU_R1206  [R1206]
PZDFB  DIODE-MINIMELF  [MINIMELF]
VDZ1  DIODE-MINIMELF  [MINIMELF]
VENTILATOR  PINHD-1X2  [1X02]
VQ1  BC847  BC847ALT1SMD  [SOT23]
VRB  R-EU_R1206  [R1206]
VRT  R-EU_R1206  [R1206]

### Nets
BATT-: P_Q2.3(E) PCOUT.- PCT1.2 PDHOT.A PS16.2 PZDFB.A VDZ1.A VQ1.2(E) VRB.2 ; also sheet 1,4,5,7
HOT: P_L1.1 PDHOT.C PQ1.2(C) PQ2.C
N$38: PQ1.3(E) PQ2.E PRE.2
N$39: L2.2 PQ1.1(B) PQ2.B PSOK2.3(EMIT)
N$41: PSOK2.2(C) PSR23.2 PZDFB.C
N$42: PSOK2.1(A) PSR22.2
N$43: L2.1 PCB.2 PCT1.1 PS16.1
N$53: P_Q2.2(C) VENTILATOR.2 VQ1.3(C)
PLUS11: PCB.1 PRE.1 PSOK2.4(COL) PSR22.1 PSR23.1 VRT.1 ; also sheet 1,4,5,7
V_VENT: P_L1.2 PCOUT.+ VENTILATOR.1 ; also sheet 7
VENTB: P_Q2.1(B) VQ1.1(B) VRB.1 ; also sheet 4
VENTMID: VDZ1.C VRT.2 ; also sheet 4

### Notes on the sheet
- V_VENT
- OK0-OK9

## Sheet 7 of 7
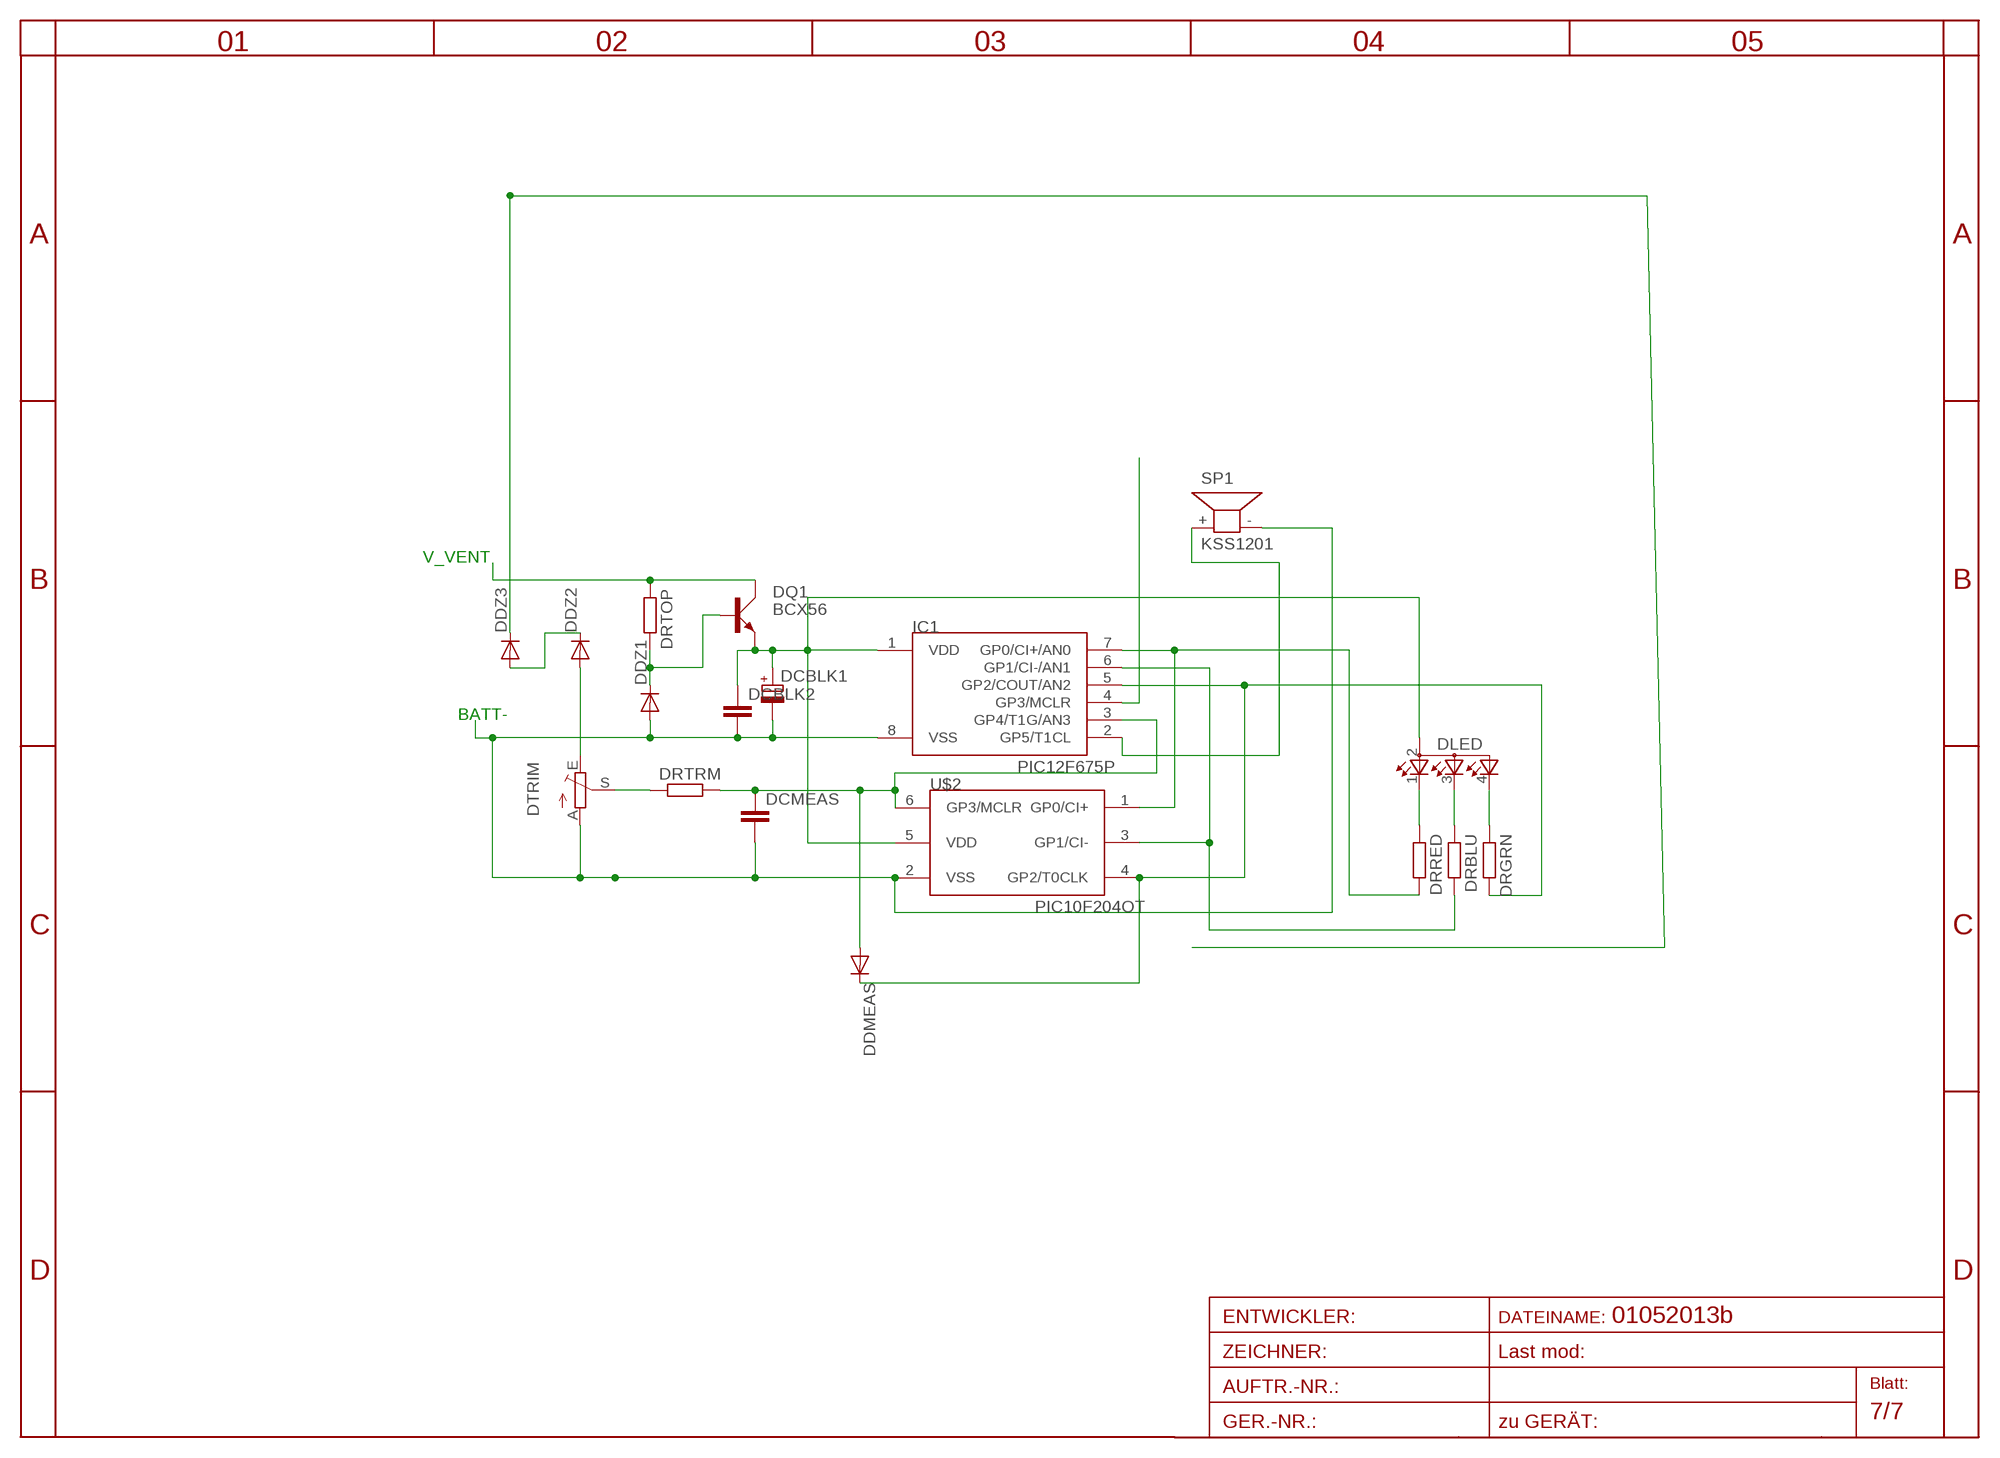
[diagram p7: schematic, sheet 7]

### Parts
DCBLK1  CPOL-EUE5-6  [E5-6]
DCBLK2  C-EUC1206  [C1206]
DCMEAS  C-EUC1206  [C1206]
DDMEAS  DIODE-MINIMELF  [MINIMELF]
DDZ1  DIODE-MINIMELF  [MINIMELF]
DDZ2  DIODE-MINIMELF  [MINIMELF]
DDZ3  DIODE-MINIMELF  [MINIMELF]
DLED  TOPLED-3  [P-LCC-4-3]
DQ1  BCX56  [SOT223]
DRBLU  R-EU_R1206  [R1206]
DRGRN  R-EU_R1206  [R1206]
DRRED  R-EU_R1206  [R1206]
DRTOP  R-EU_R1206  [R1206]
DRTRM  R-EU_R1206  [R1206]
DTRIM  TRIM_EU-EVND_H  [EVND8AA]
IC1  PIC12F675P  [DIL8]
SP1  KSS1201  [KSS1201]
U$2  PIC10F204OT  [SOT23-6]

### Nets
BATT-: DCBLK1.- DCBLK2.2 DCMEAS.2 DDZ1.A DTRIM.A IC1.8(VSS) SP1.- U$2.2(VSS) ; also sheet 1,4,5,6
GP3: IC1.4(GP3/MCLR) ; also sheet 4
N$34: DCBLK1.+ DCBLK2.1 DLED.2(A2) DQ1.3(E) IC1.1(VDD) U$2.5(VDD)
N$35: DRRED.2 IC1.7(GP0/CI+/AN0) U$2.1(GP0/CI+)
N$36: DRBLU.2 IC1.6(GP1/CI-/AN1) U$2.3(GP1/CI-)
N$37: DDMEAS.C DRGRN.2 IC1.5(GP2/COUT/AN2) U$2.4(GP2/T0CLK)
N$46: DDZ1.C DQ1.1(B) DRTOP.2
N$47: DLED.1(CRED) DRRED.1
N$48: DLED.3(CBLUE) DRBLU.1
N$49: DLED.4(CGREEN) DRGRN.1
N$69: DDZ2.A DTRIM.E
N$75: DCMEAS.1 DDMEAS.A DRTRM.2 IC1.3(GP4/T1G/AN3) U$2.6(GP3/MCLR)
N$83: DDZ2.C DDZ3.A
N$96: IC1.2(GP5/T1CL) SP1.+
PLUS11: DDZ3.C ; also sheet 1,4,5,6
V_TOT: DRTRM.1 DTRIM.S
V_VENT: DQ1.2(C) DRTOP.1 ; also sheet 6

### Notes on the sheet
- V_VENT
- BATT-

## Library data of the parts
(BATT+) (BATT-) C_VIN+ CHARGE JP1-JP13 M-9BAT M-10BAT MINUS1- MINUS2- MINUS3- MINUS4- MINUS5- MINUS6- MINUS7- MINUS8- MINUS9- MINUS10 MINUS60 MINUS120 PLUS1+ PLUS2+ PLUS3+ PLUS4+ PLUS5+ PLUS6+ PLUS7+ PLUS8+ PLUS9+ PLUS10+ PLUS120 VIN(+) VMINUS(-) VOUT(+) VOUT(+)1 VOUT(+)REG VOUT- = pinhead:PINHD-1X1: PIN HEADER
A C CDT3L1 CDT3L2 CDZIO D1-D3 D9 D9A D9A1 D10 D10A D10A1 D10A2 D12-D15 D17-D30 D33-D40 D43-D46 DDMEAS DDZ1-DDZ3 PDHOT PZDFB SDL1 SDL2 SDZH1 SDZH2 VD2 VD-S1 VD-S2 VDIO VZDHV = diode:DIODE-: DIODE
A..C LED4-LED7 LED8X LED9 LED9X LED10 LED10X SLED1 = led:LED: LED
B1 B2 B5 B7 B9 B11 = rectifier:2KBP: RECTIFIER grid 3 x 3,81 mm
B3 B4 B6 B8 B10 B12 = rectifier:MB*S: Bridge Rectifier Source: http://www.fairchildsemi.com/ds/MB/MB6S.pdf
C1 C2 CCIO CCIO1 DCBLK2 DCMEAS PCB PCT1 VCHI VCHI1 VCIO VCLO VCLO1 = rcl:C-EU: CAPACITOR, European symbol
C-1083 V-1083 = linear-technology-2:LT1083*: 7.5A Low Dropout Positive Adjustable Regulators
C-SO8 C-TO92 TO92S V-SO8 = v-reg-3:LM317L: Adjustable Voltage Regulator, 1.2V to 37V, 100mA
C-TS V-TS = v-reg:LM317TS: VOLTAGE REGULATOR
C. CDZHV = diode-1:1N4148: DIODE
CCOUT DCBLK1 PCOUT VCAD VCIN VCOUT = rcl:CPOL-EU: POLARIZED CAPACITOR, European symbol
CD4 = diode:BAS40-04: Silicon Schottky Diodes General-purpose diode for high-speed switching
CMABDT VMABDT = v-reg:LM317?*: 500 mA Adjustable Output Positive Voltage Regulator Source: http://www.onsemi.co.jp .. LM317M-D.PDF
CO1 CRHV CRLM1-CRLM3 CRT2H DRBLU DRGRN DRRED DRTOP DRTRM FRBOUT FRFS FRGS FRGTE FRHVL FRHVT FRIO PRE PS16 PSR22 PSR23 SRB SRC SRHOKD SRLOKD SROH SROL VO1 VO2 VR1-VR3 VR3X VR4-VR8 VR8X VR9-VR17 VR20-VR77 VR79-VR81 VR(+)10 VR(-)10 VRB VRB1 VRB2 VRB(+B)10 VRB(+C)10 VRB(-)1 VRB(-)10 VRHV VRSHNT VRT VRT1-VRT4 = rcl-2:R-EU_: RESISTOR, European symbol
CQHV CQREG = transistor-power:BD139: NPN TRANSISTOR
CTRIM2 CTRIM3 DTRIM STRIM01 TRIM1-9 TRIM2-7 TRIM2-9 TRIM3-9 TRIM3X TRIM5X TRIM7X TRIM8X TRIM9X TRIM10X TRIM10X1 VPOT1 VPOT2 VTRIM1 = pot:TRIM_EU-: POTENTIOMETER
DLED = led:TOPLED-3: OSRAM - Hyper Multi TOPLED® (RGB) LB E673, LV E673, LT E673 - Power TOPLED® Enhanced optical Power LED (HOP2000) LS E67B, LA E67B, LO E67B, LY E67B - Hyper Multi TOPLED® Enhanced optical Power LED (HOP2000 / ATON®) LATB T66B - Hyper Multi TOPLED® Hyper-Bright LED LATB T686 Source: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
DQ1 P_Q2 U$3 = transistor-power:BCX56
F2 VFUSE = fuse:SHK20Q: FUSE HOLDER 5 x 20 mm, SH contact, E1207 Buerklin 64G6061
FCB = rcl-2:C-EU: CAPACITOR, European symbol
FDZHV = diode-1:ZENER-DIODE: Z-Diode
FQ1 = transistor-pnp:BC807*: PNP Transistror
FQFET = transistor-fet:FDD4141: P-Channel PowerTrench® MOSFET Source: FDD4141.pdf
FQHVU = transistor:BC846: NPN TRANSISTOR
IC1 = microchip-5:PIC12F6*: uPC nW 1k Program Flash memory 2x Timer Comparator 10b A/D converter/ 4xIN
IC2 = linear:LM321?*: Low Power Single Op Amp Source: http://cache.national.com/ds/LM/LM321.pdf
JP14 JP17 = pinhead:PINHD-1X2: PIN HEADER
K1 K2 = relay:G2R: RELAY 1 x switch, Omron
L2 P_L1 = rcl:L-EU: INDUCTOR, European symbol
OK2X OK3 OK4X OK5X OK6X OK7 OK8X OK9X PSOK2 SOK1 = optocoupler:SFH618?*: Optocoupler, Phototransistor Output, Low Input Current Source: http://www.vishay.com/docs/83673/sfh618.pdf
OUT+ VIN(-) VIN(-)1 VIN+1 = pinhead(2):PINHD-1X1: PIN HEADER
PQ1 PQ2 Q4 Q10 Q11 Q13 Q19 Q30-Q36 Q(+)1 SQ1 = transistor-pnp:BC857*: PNP Transistror
Q1 Q21 Q29 Q38-Q44 = transistor-power:TIP142: NPN DARLINGTON TRANSISTOR
Q1T Q2S Q2T Q3 Q7-Q9 Q10S Q15-Q18 Q20 Q22-Q28 = transistor-power:TIP120: NPN DARLINGTON TRANSISTOR
Q2 Q6 Q12 Q37 Q(-)10 VQ1 = transistor-npn:BC847*: NPN Transistor
Q45 = transistor-power:TIP42C: PNP TRANSISTOR
Q46 = transistor-power:TIP147: PNP DARLINGTON TRANSISTOR
R2-R5 R13 R14 R16 R18 R21 R24 VR-B = rcl:R-EU_: RESISTOR, European symbol
S1 = switch:320-938: TOGGLE SWITCH distributor RS Components
SP1 SP2 SP10 = buzzer:KSS1201: SPEAKER
U$1 U$7 = microchip-3:PIC10F2*: uPC nW 0,25/0,5k Program Flash memory Comparator
U$2 = microchip-5:PIC10F2*: uPC nW 0,25/0,5k Program Flash memory Comparator
U$4 = transistor-power:BCX53
V-TO1 V-TO3 = v-reg:LM317-TO3: VOLTAGE REGULATOR
VCQ = transistor-npn:BC817*: NPN Transistor
VDZ1 = diode-1:DIODE-: DIODE
VENTILATOR = pinhead(2):PINHD-1X2: PIN HEADER
VQHV = transistor-power:TIP41C: NPN TRANSISTOR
